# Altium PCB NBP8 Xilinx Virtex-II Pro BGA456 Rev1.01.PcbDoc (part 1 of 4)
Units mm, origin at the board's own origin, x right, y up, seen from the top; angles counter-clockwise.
Board outline 69 x 99.5 mm, 8 copper layers (Top Layer, InternalPlane1, InternalPlane2, MidLayer1, MidLayer2, MidLayer3, MidLayer4, Bottom Layer), stack 1.545 mm thick; 164 components, 314 nets, 1132 pads, 807 vias.
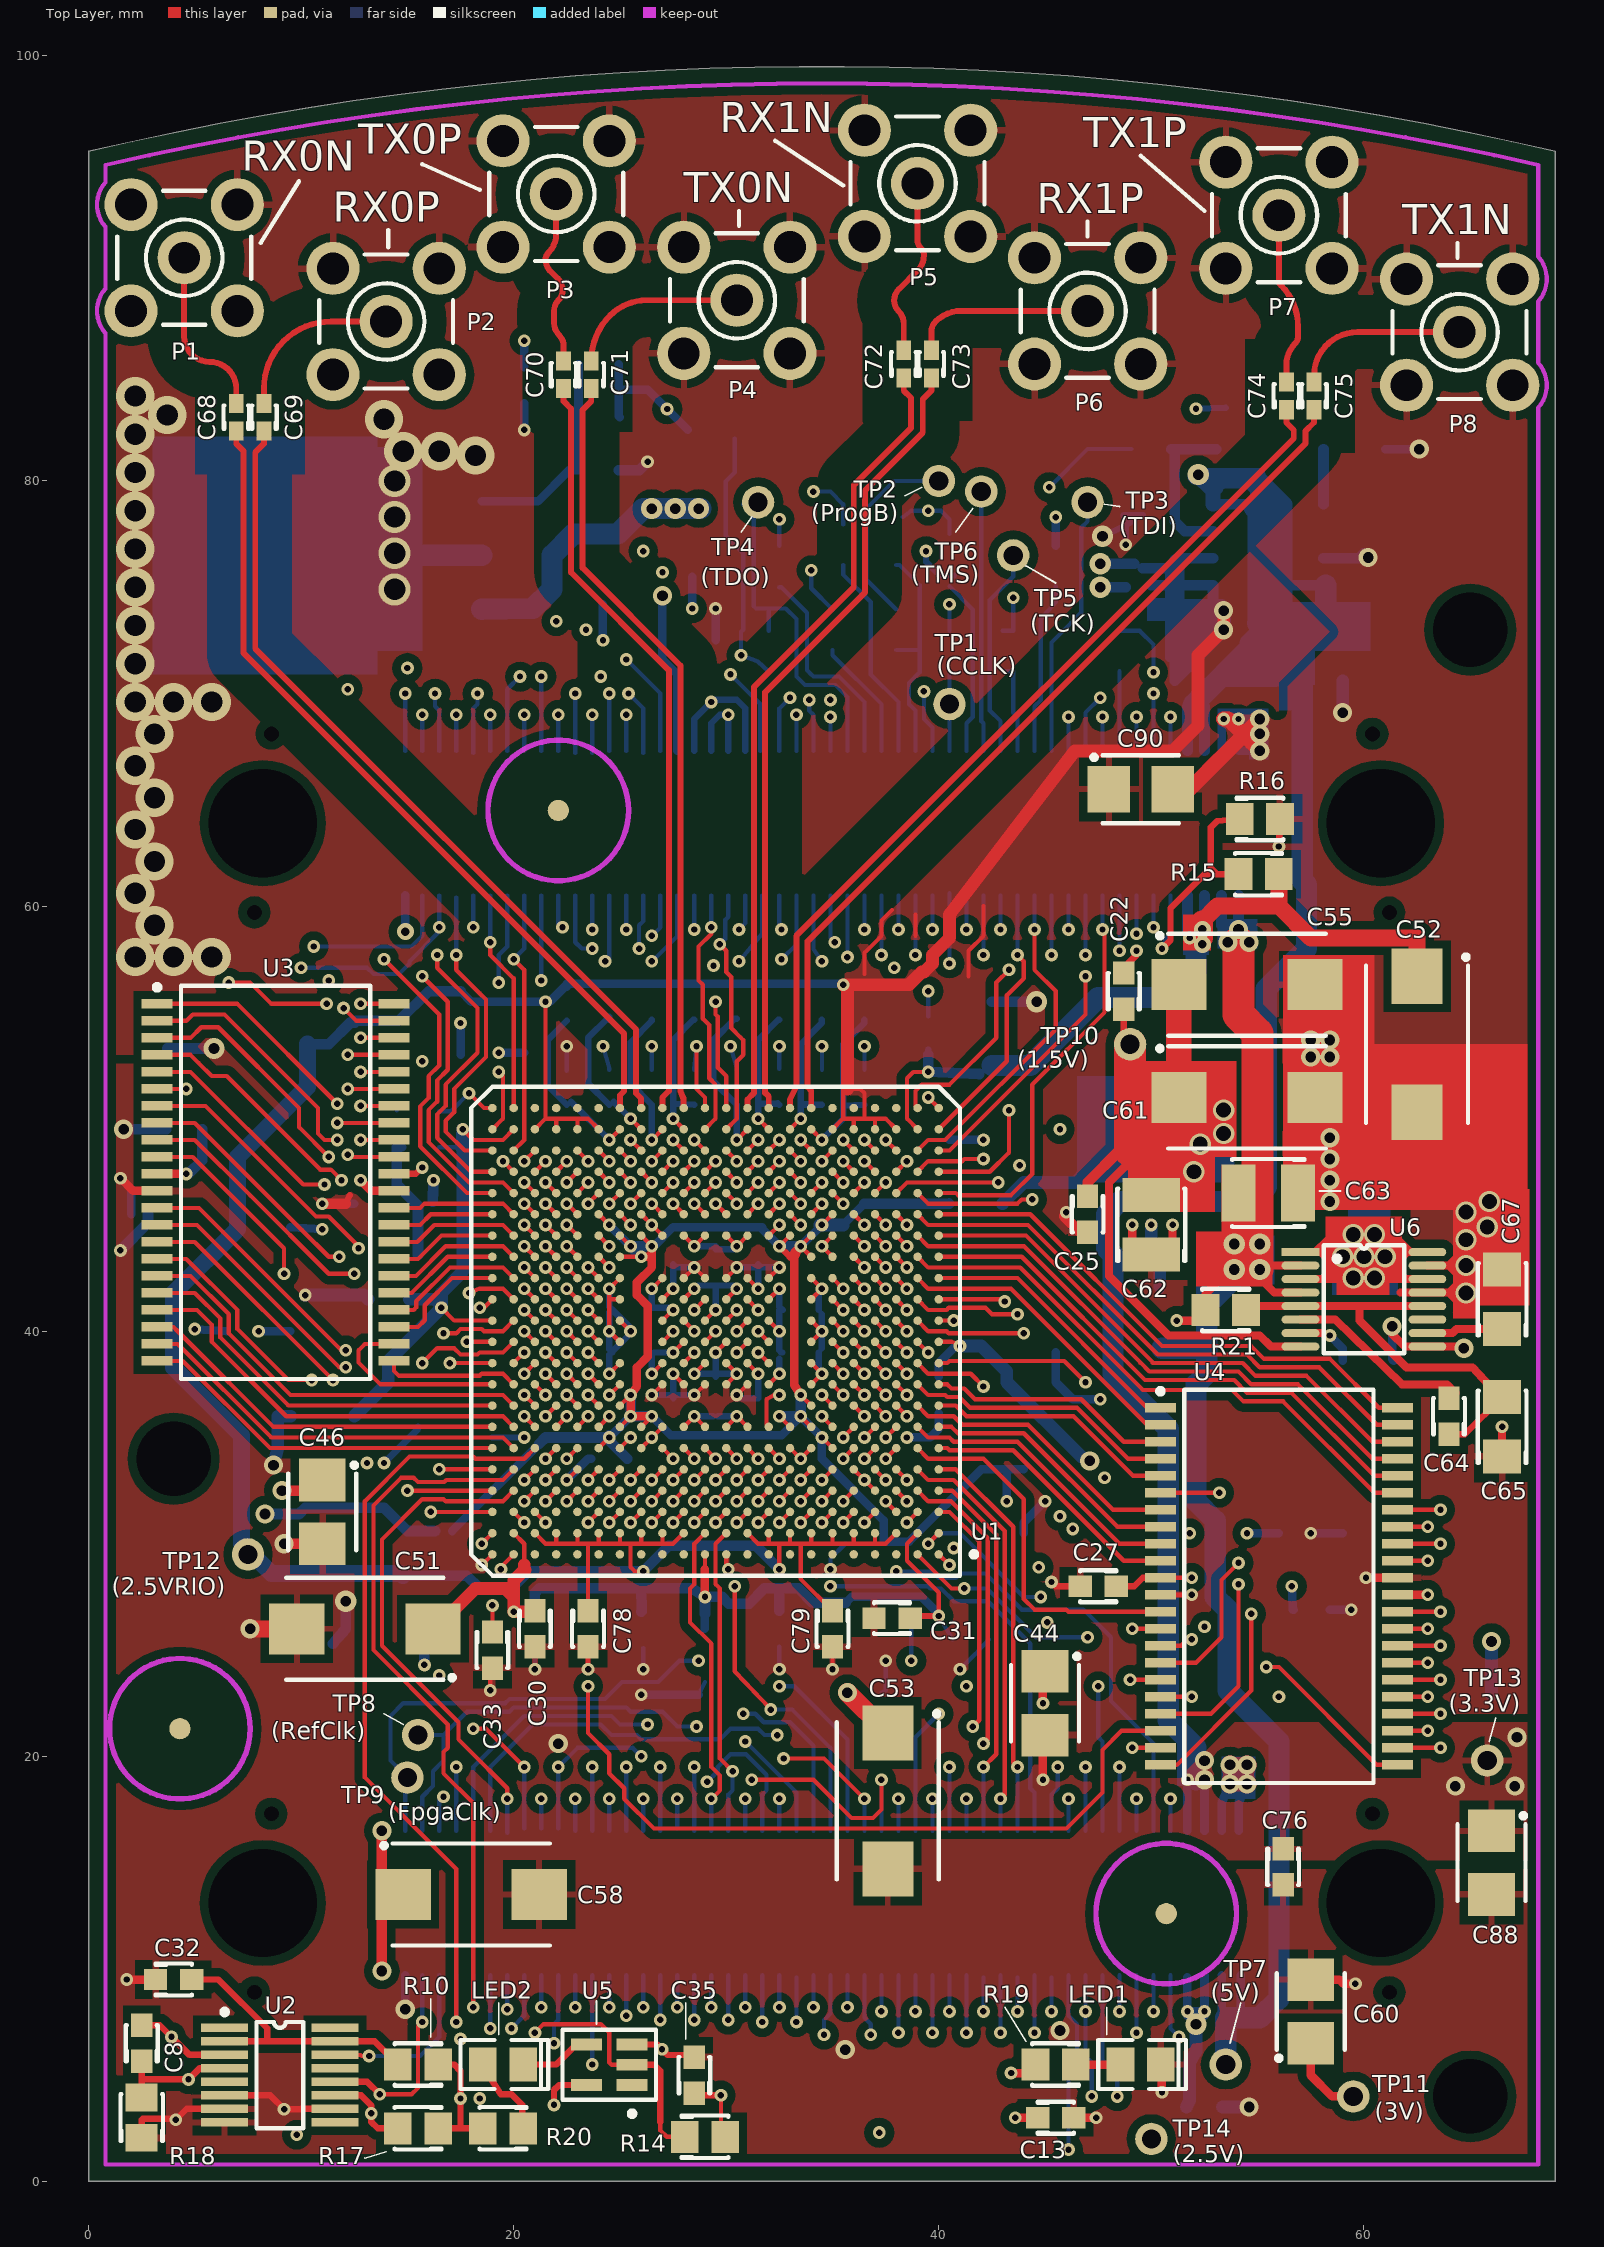
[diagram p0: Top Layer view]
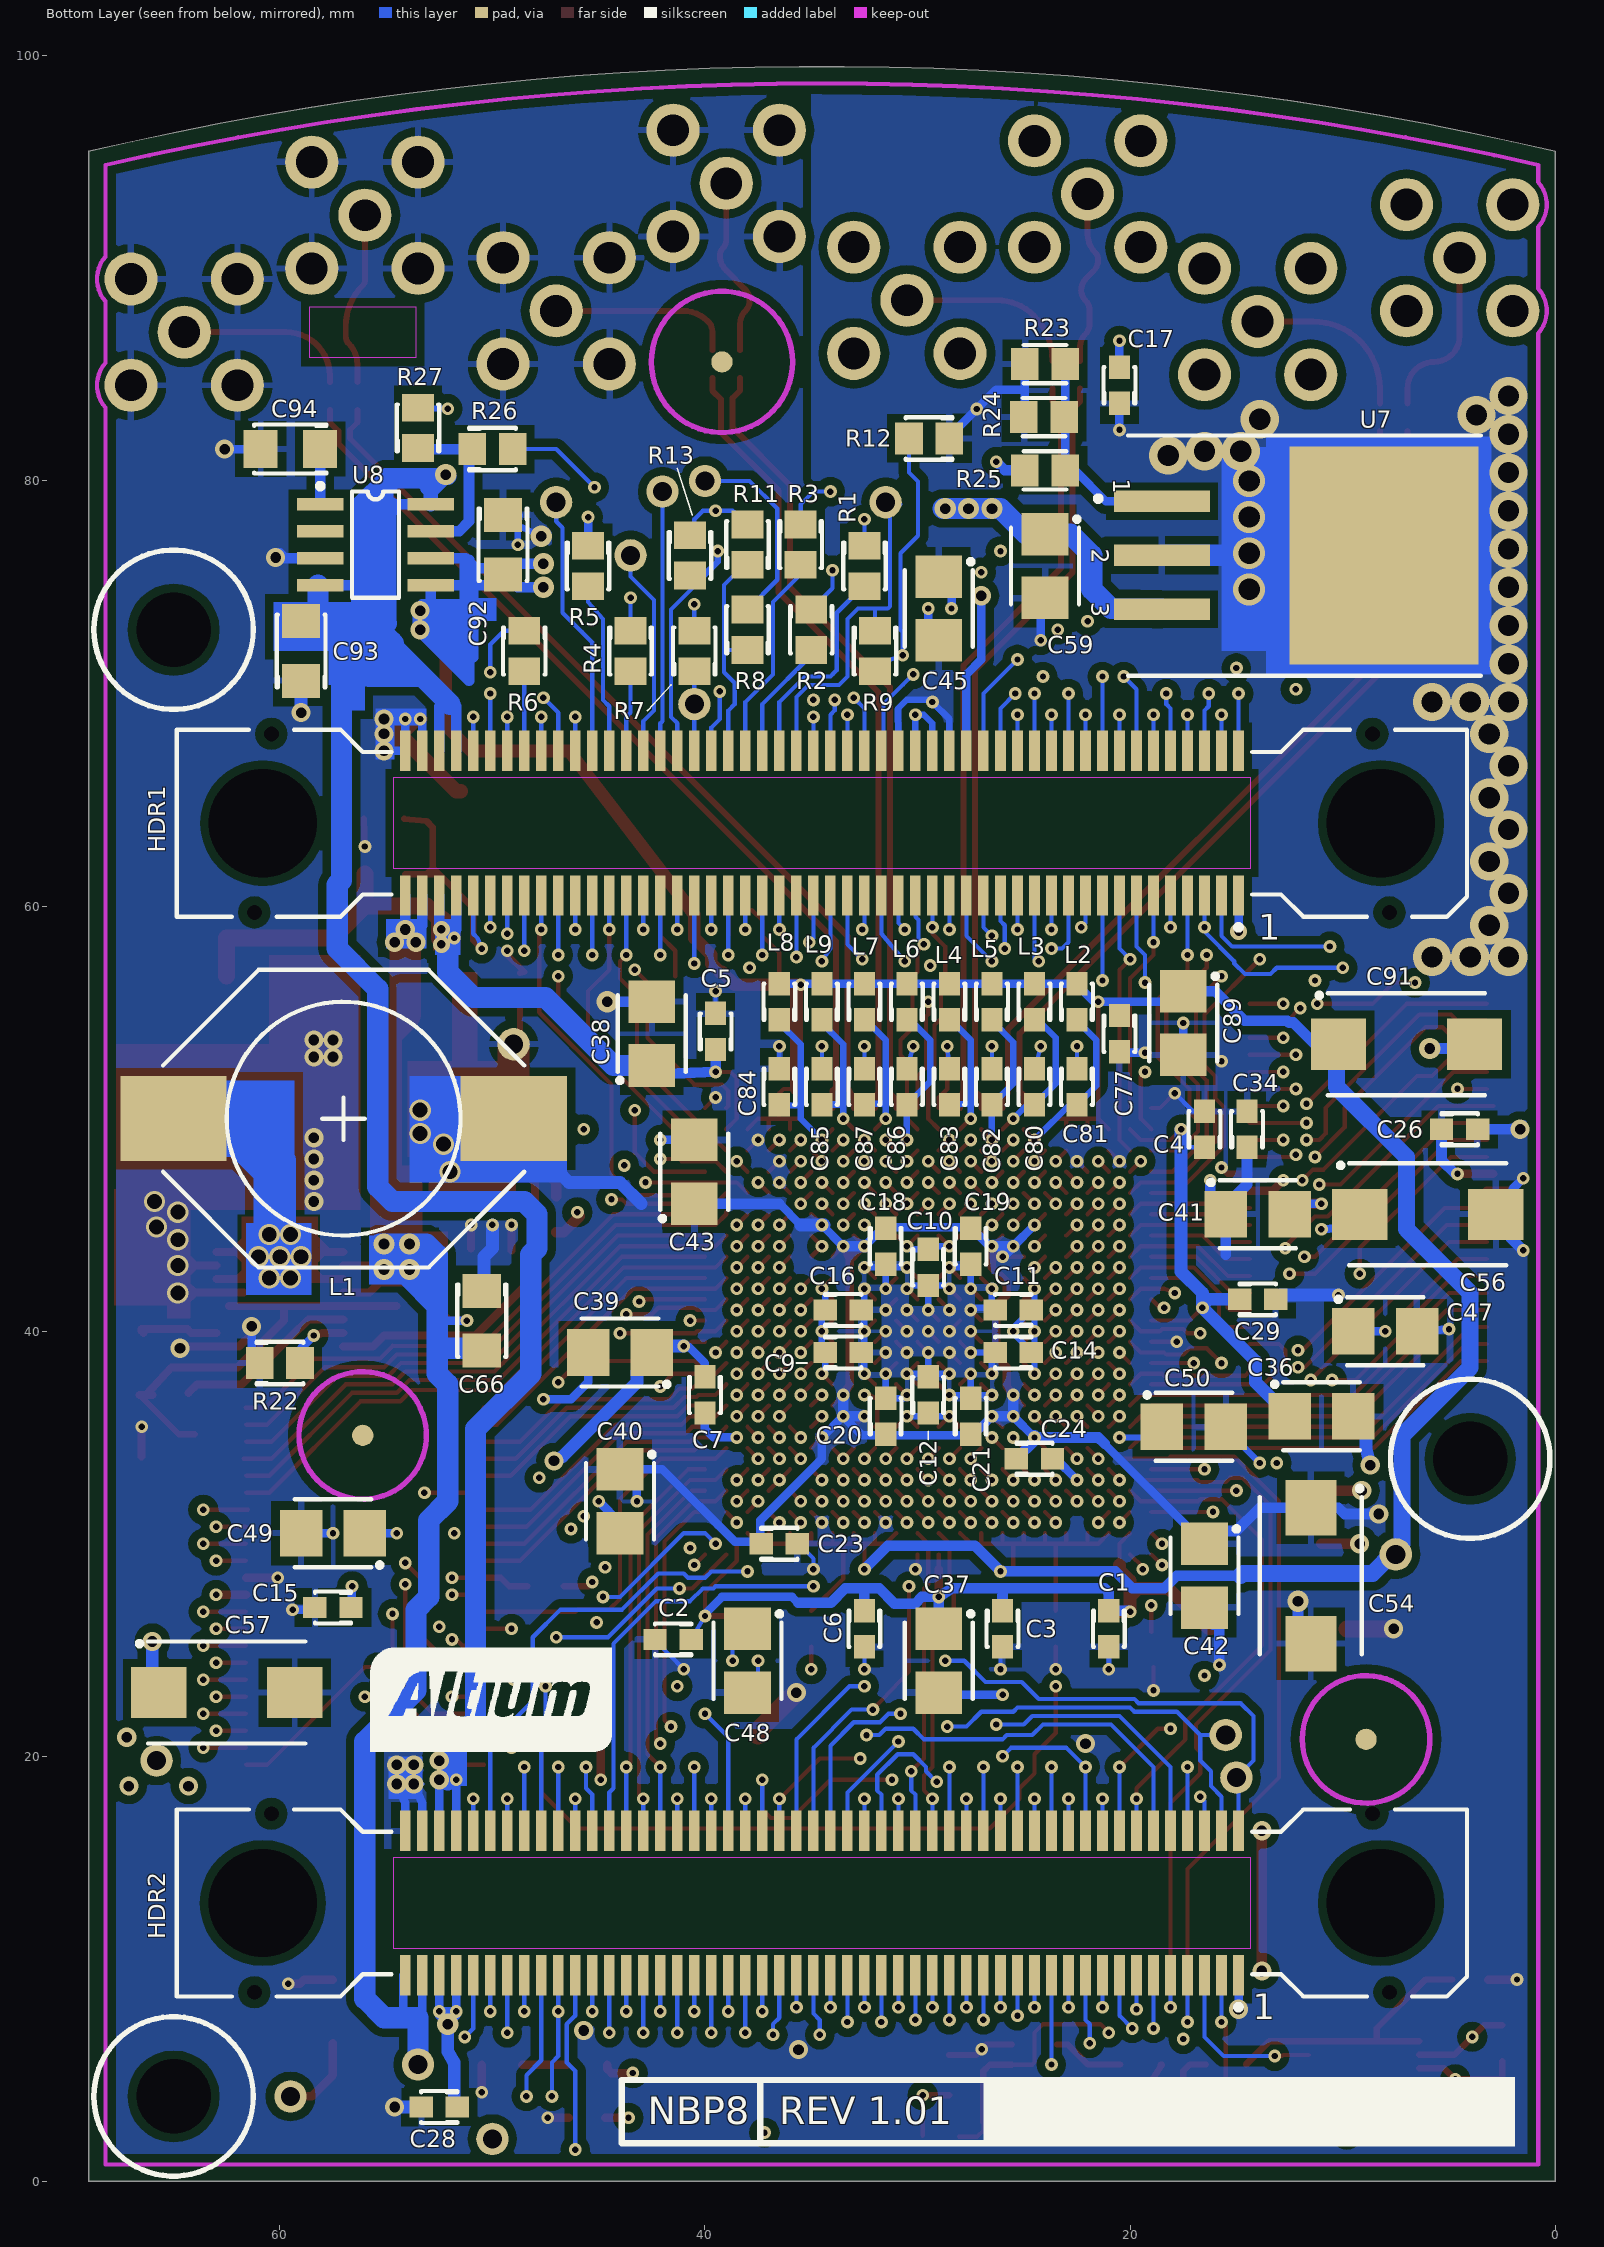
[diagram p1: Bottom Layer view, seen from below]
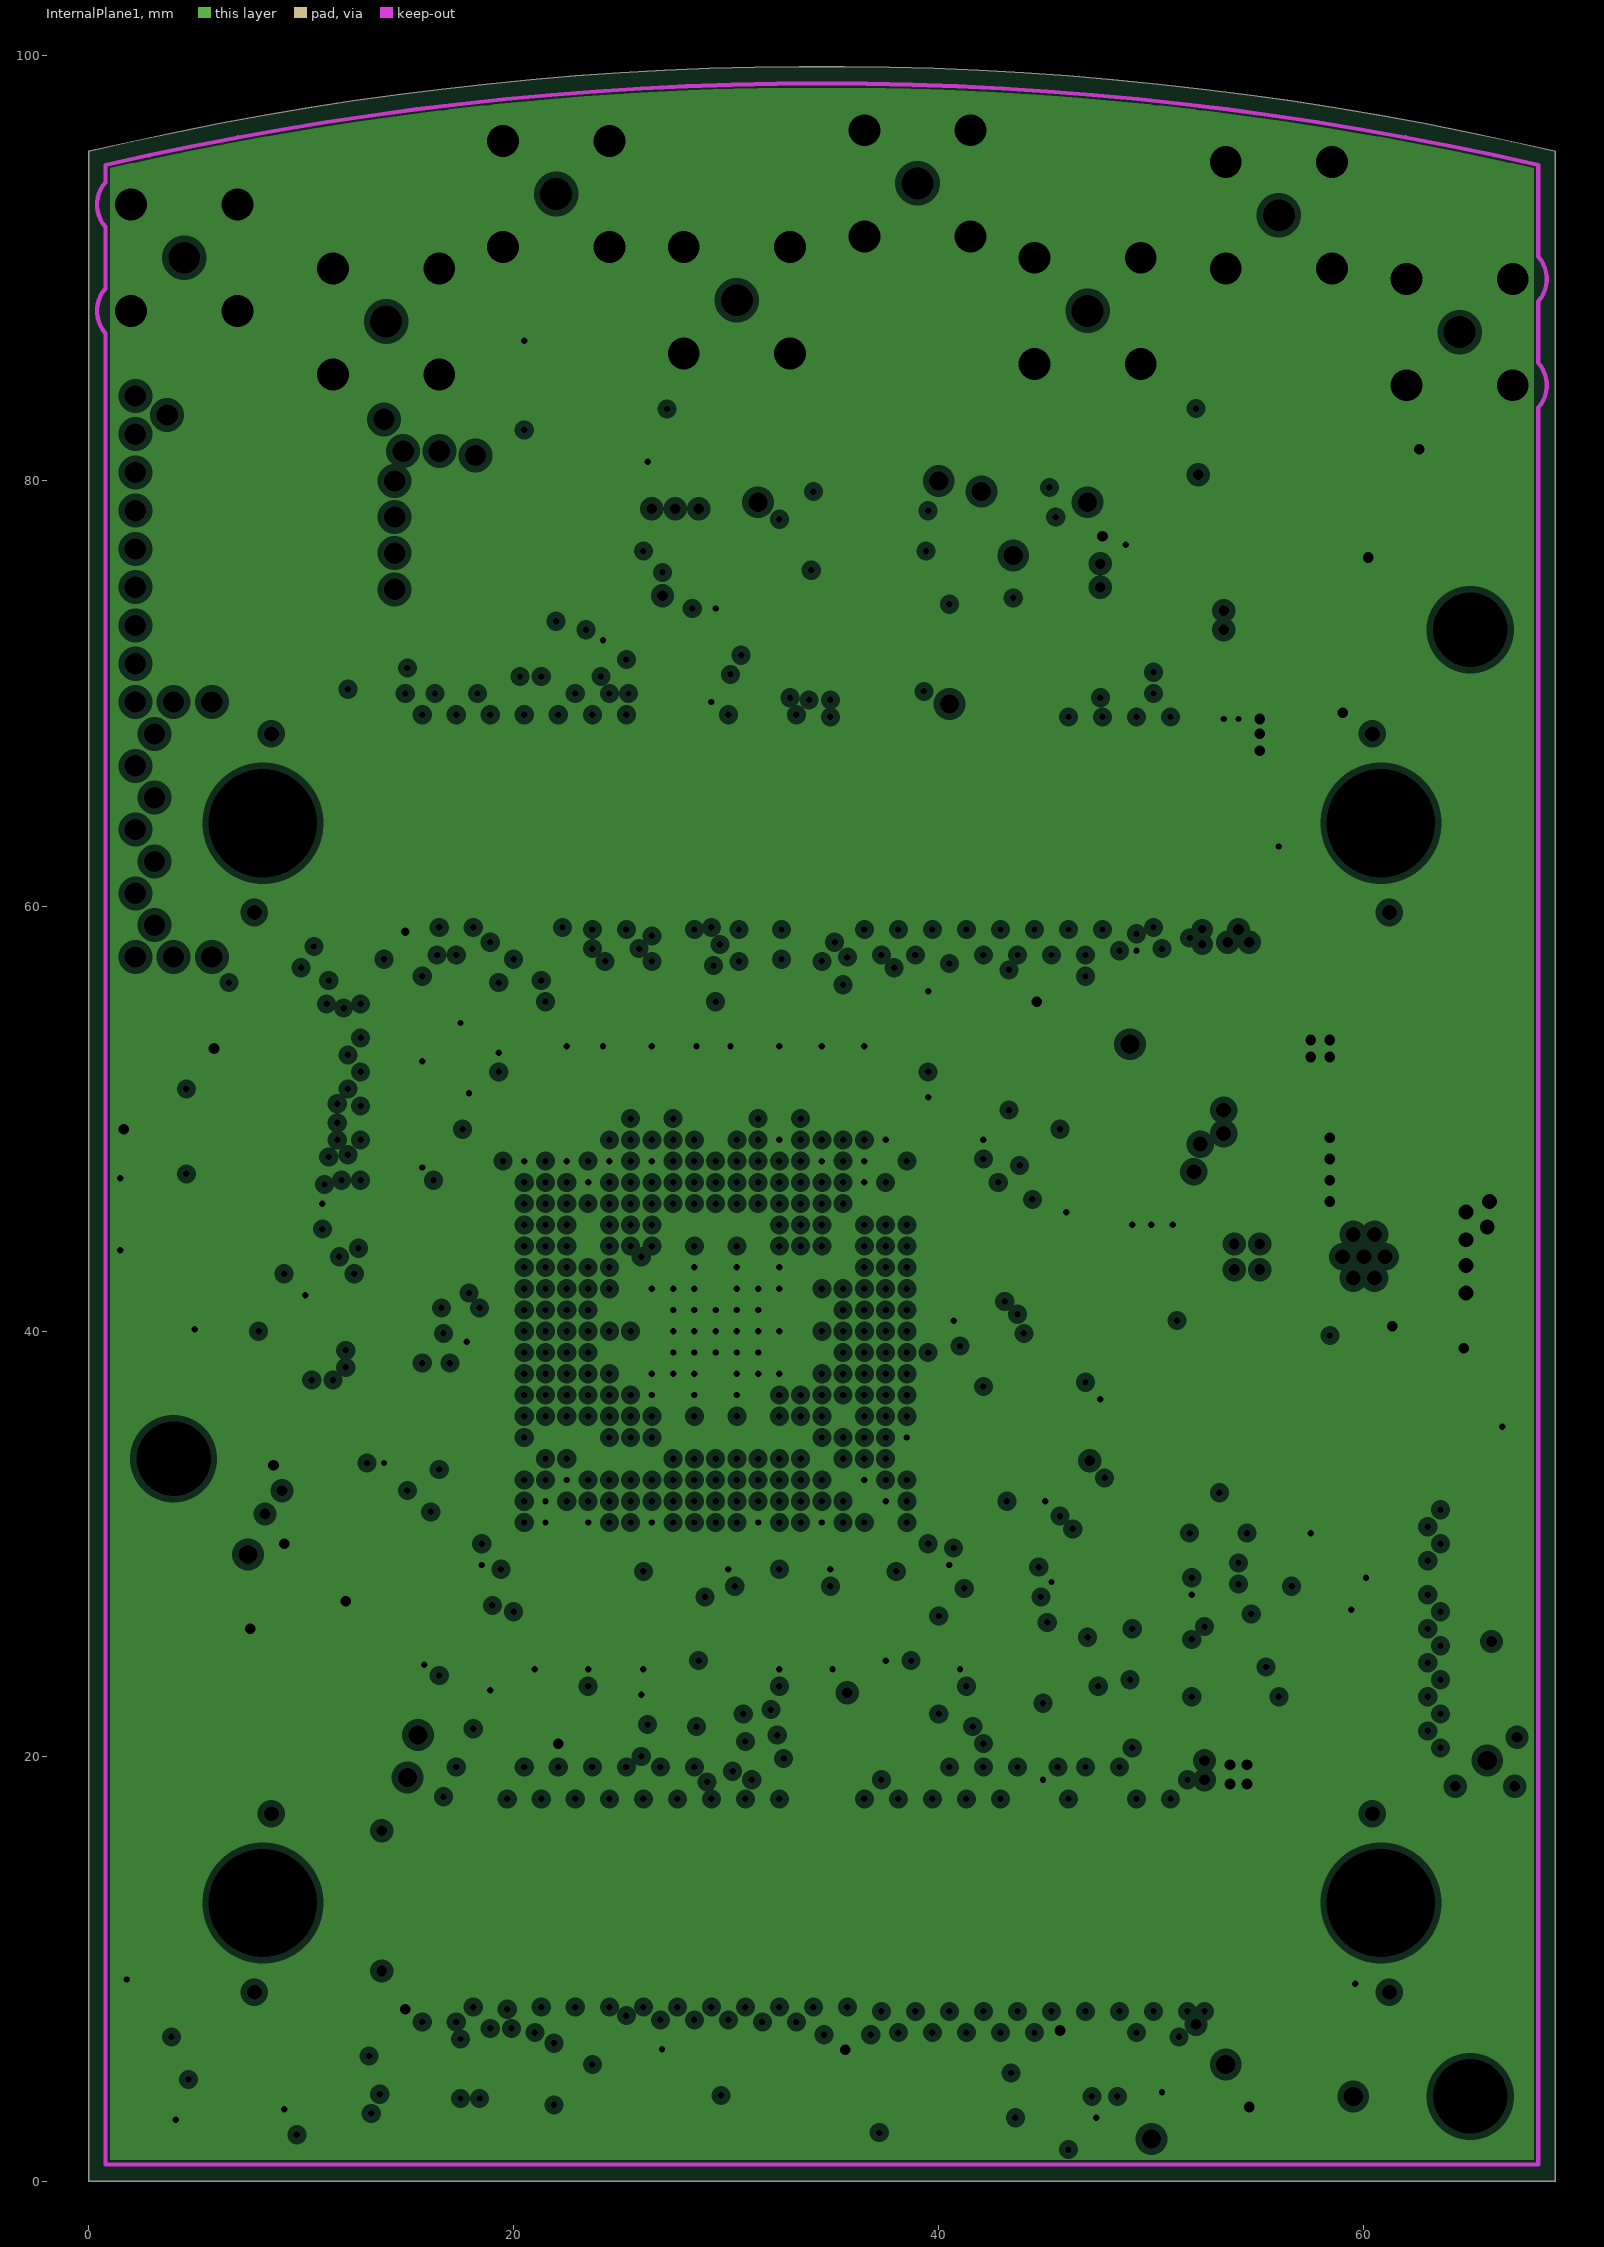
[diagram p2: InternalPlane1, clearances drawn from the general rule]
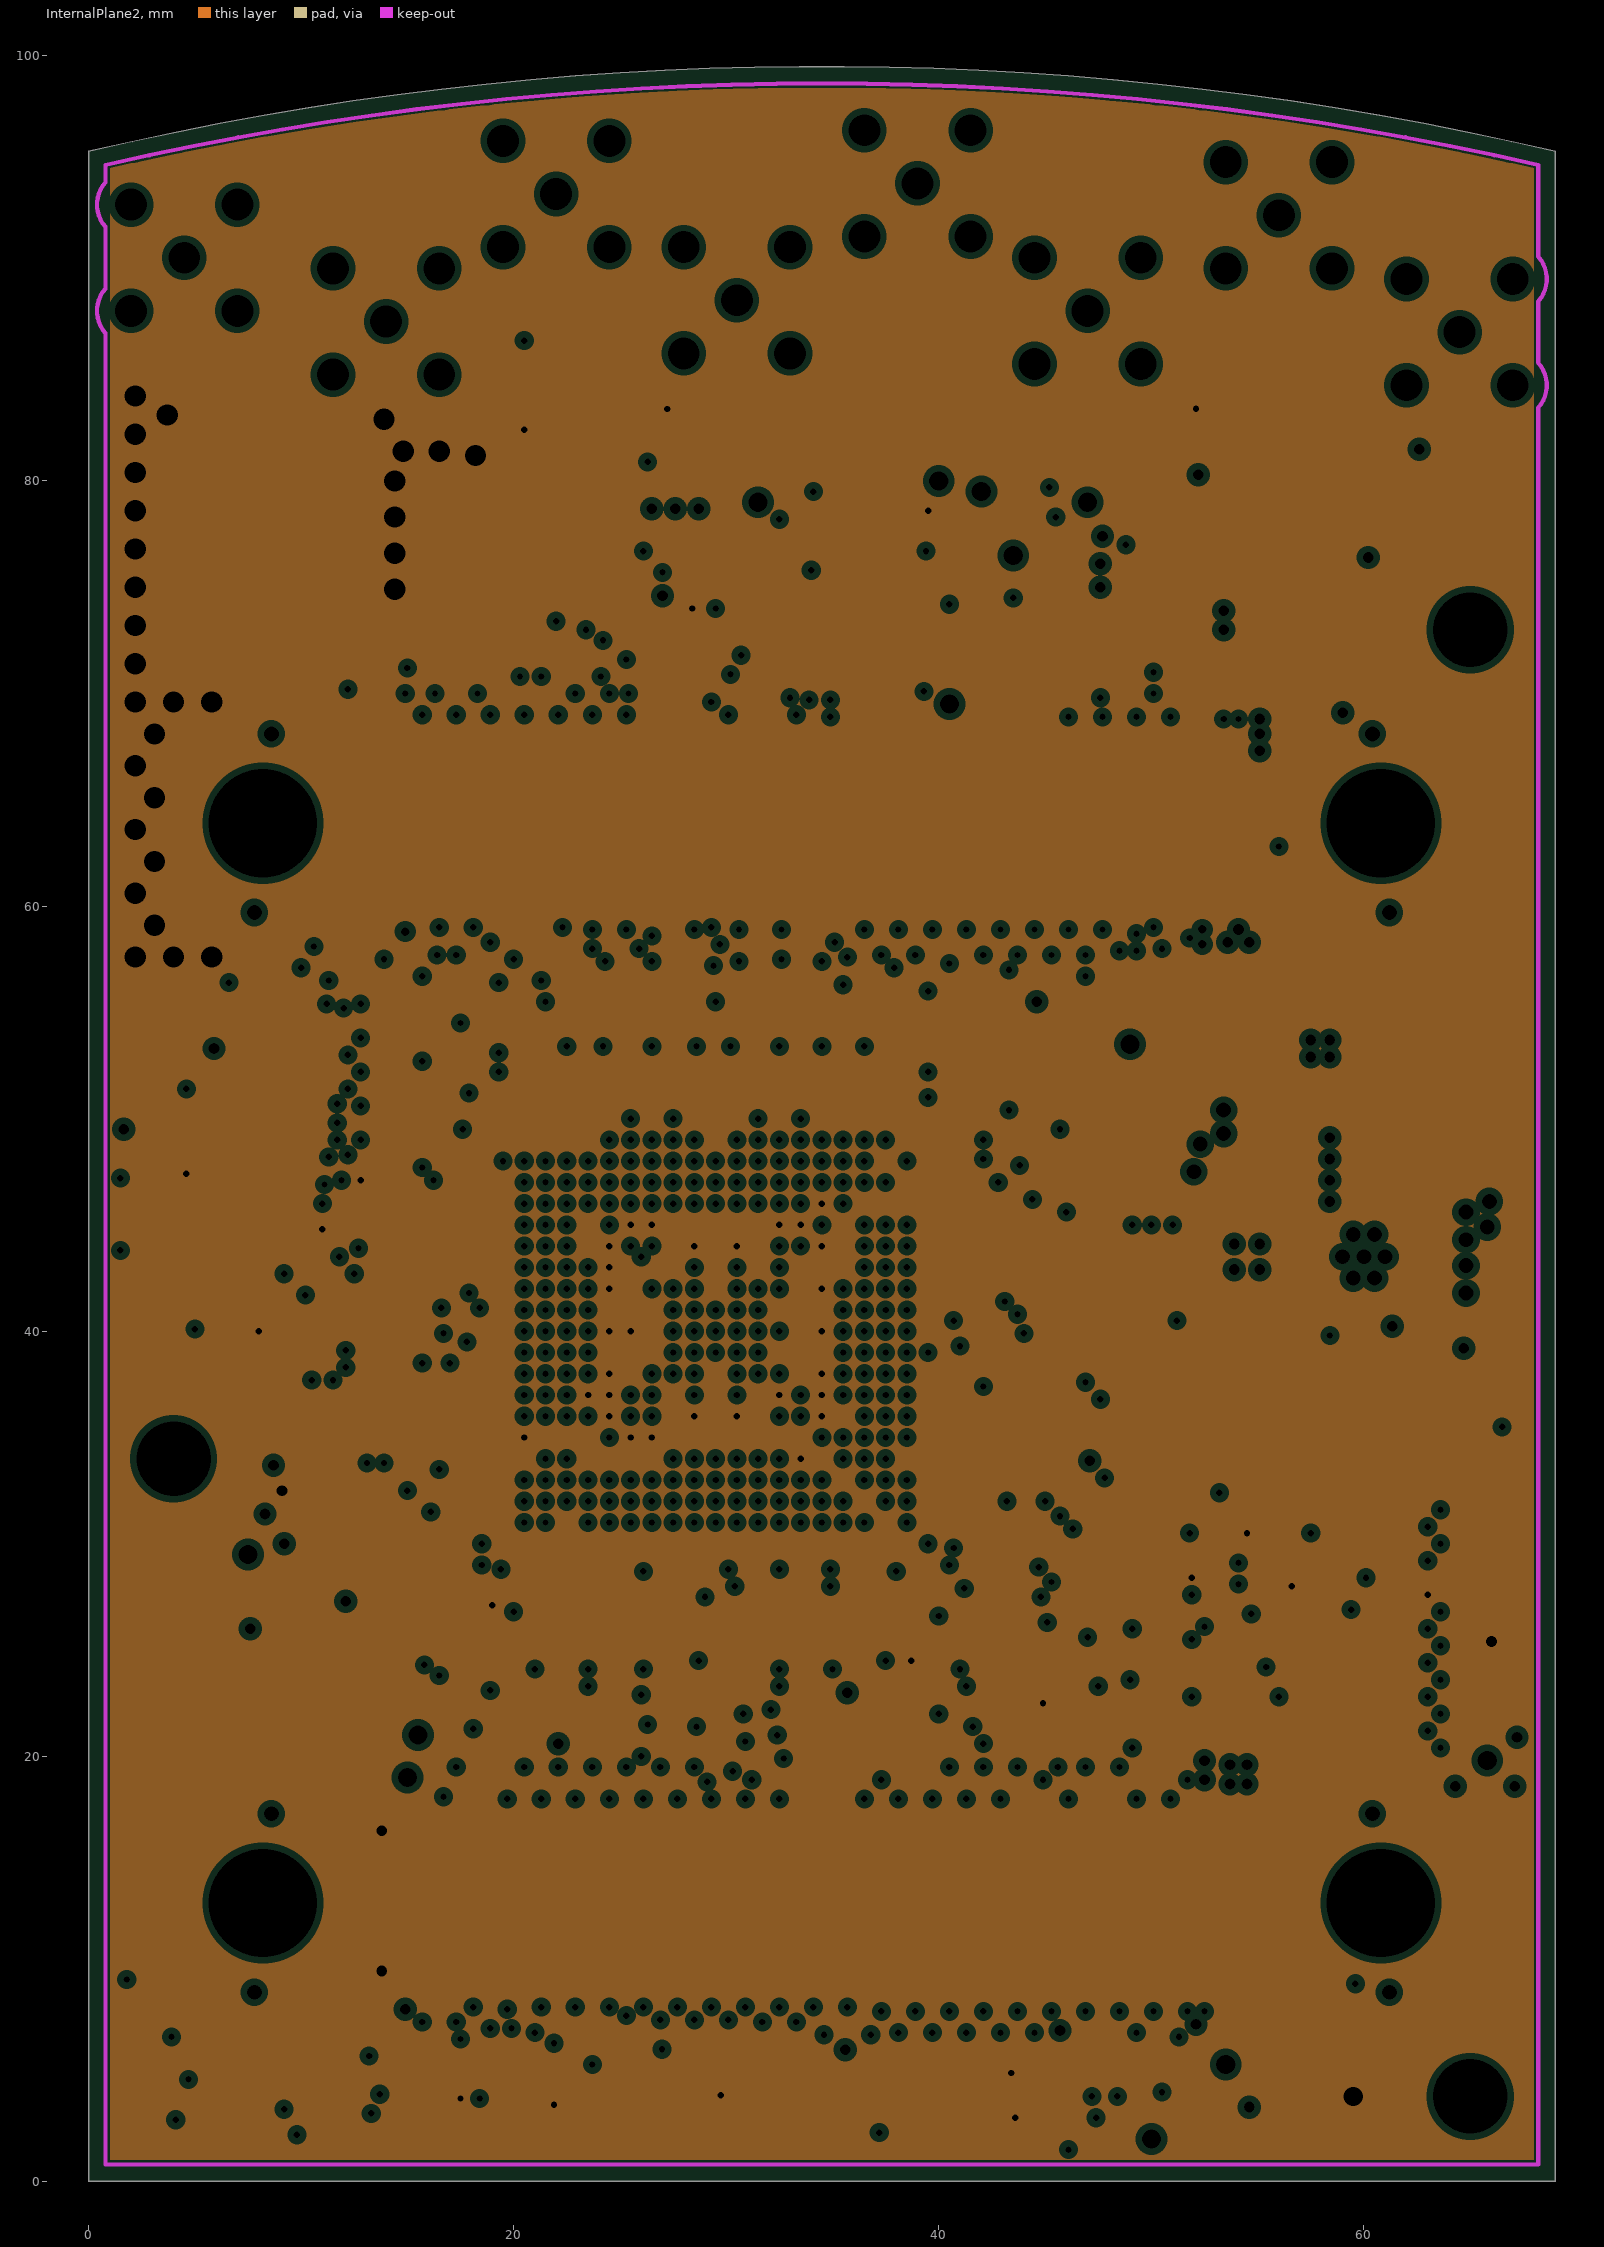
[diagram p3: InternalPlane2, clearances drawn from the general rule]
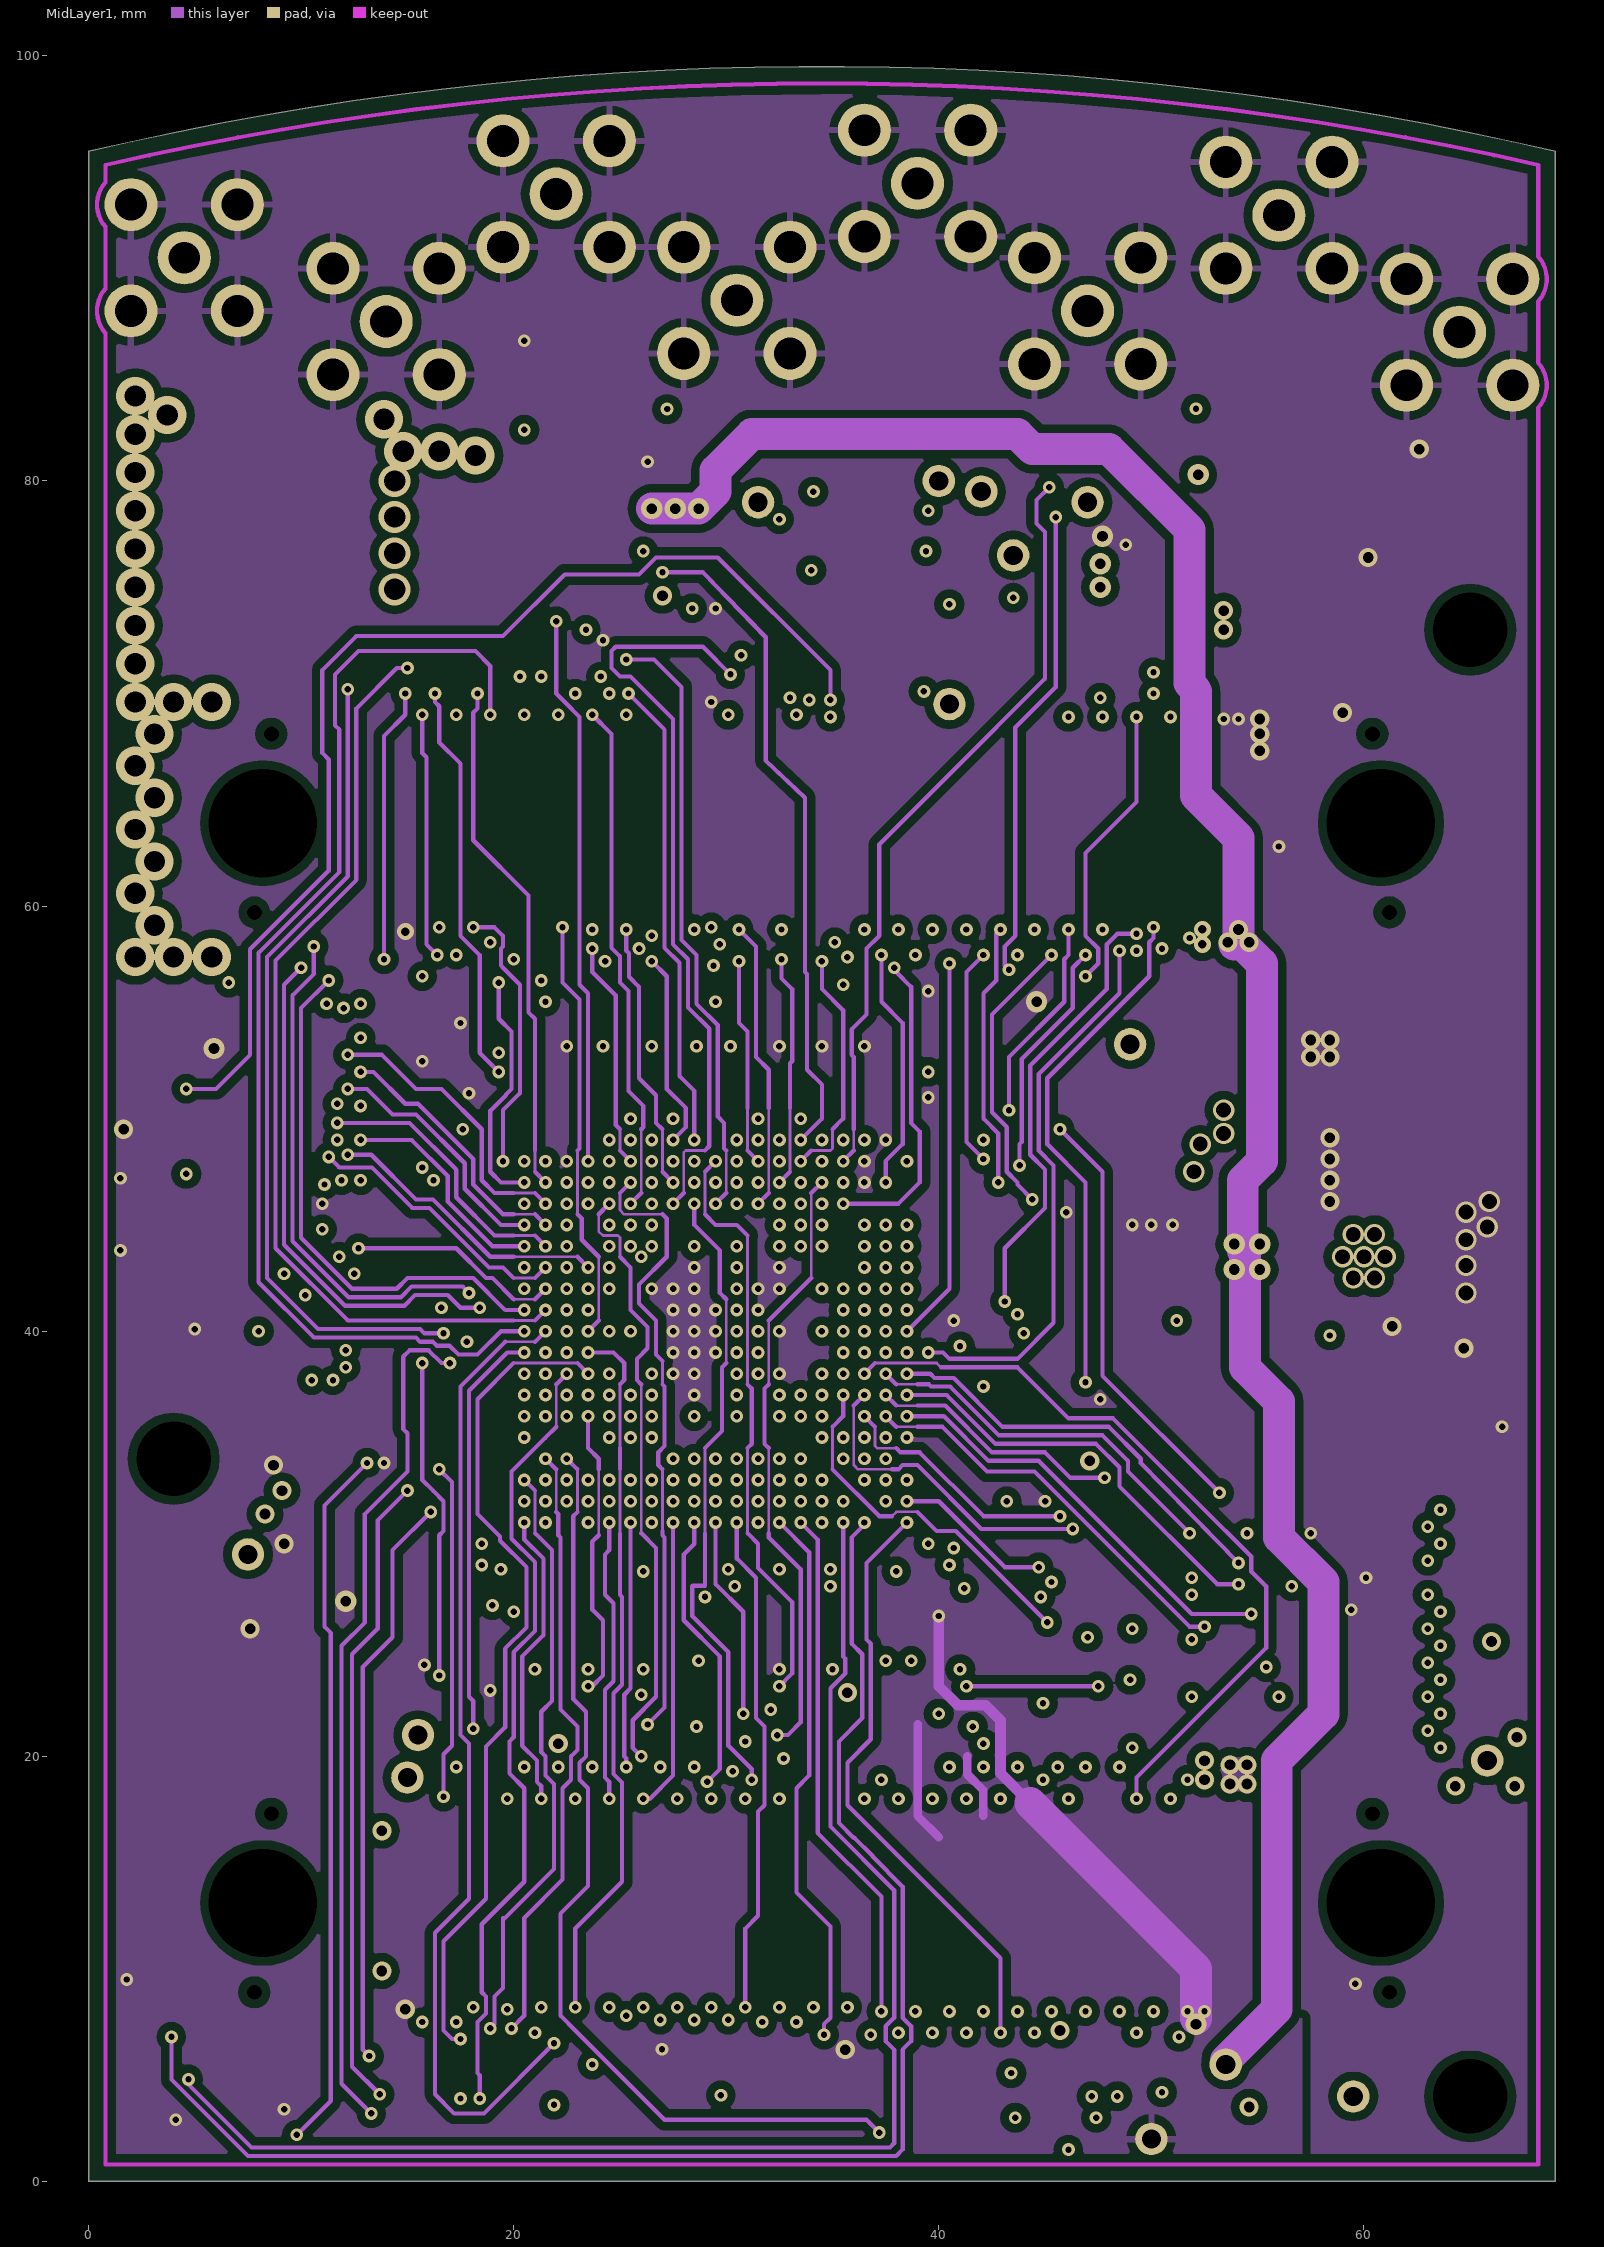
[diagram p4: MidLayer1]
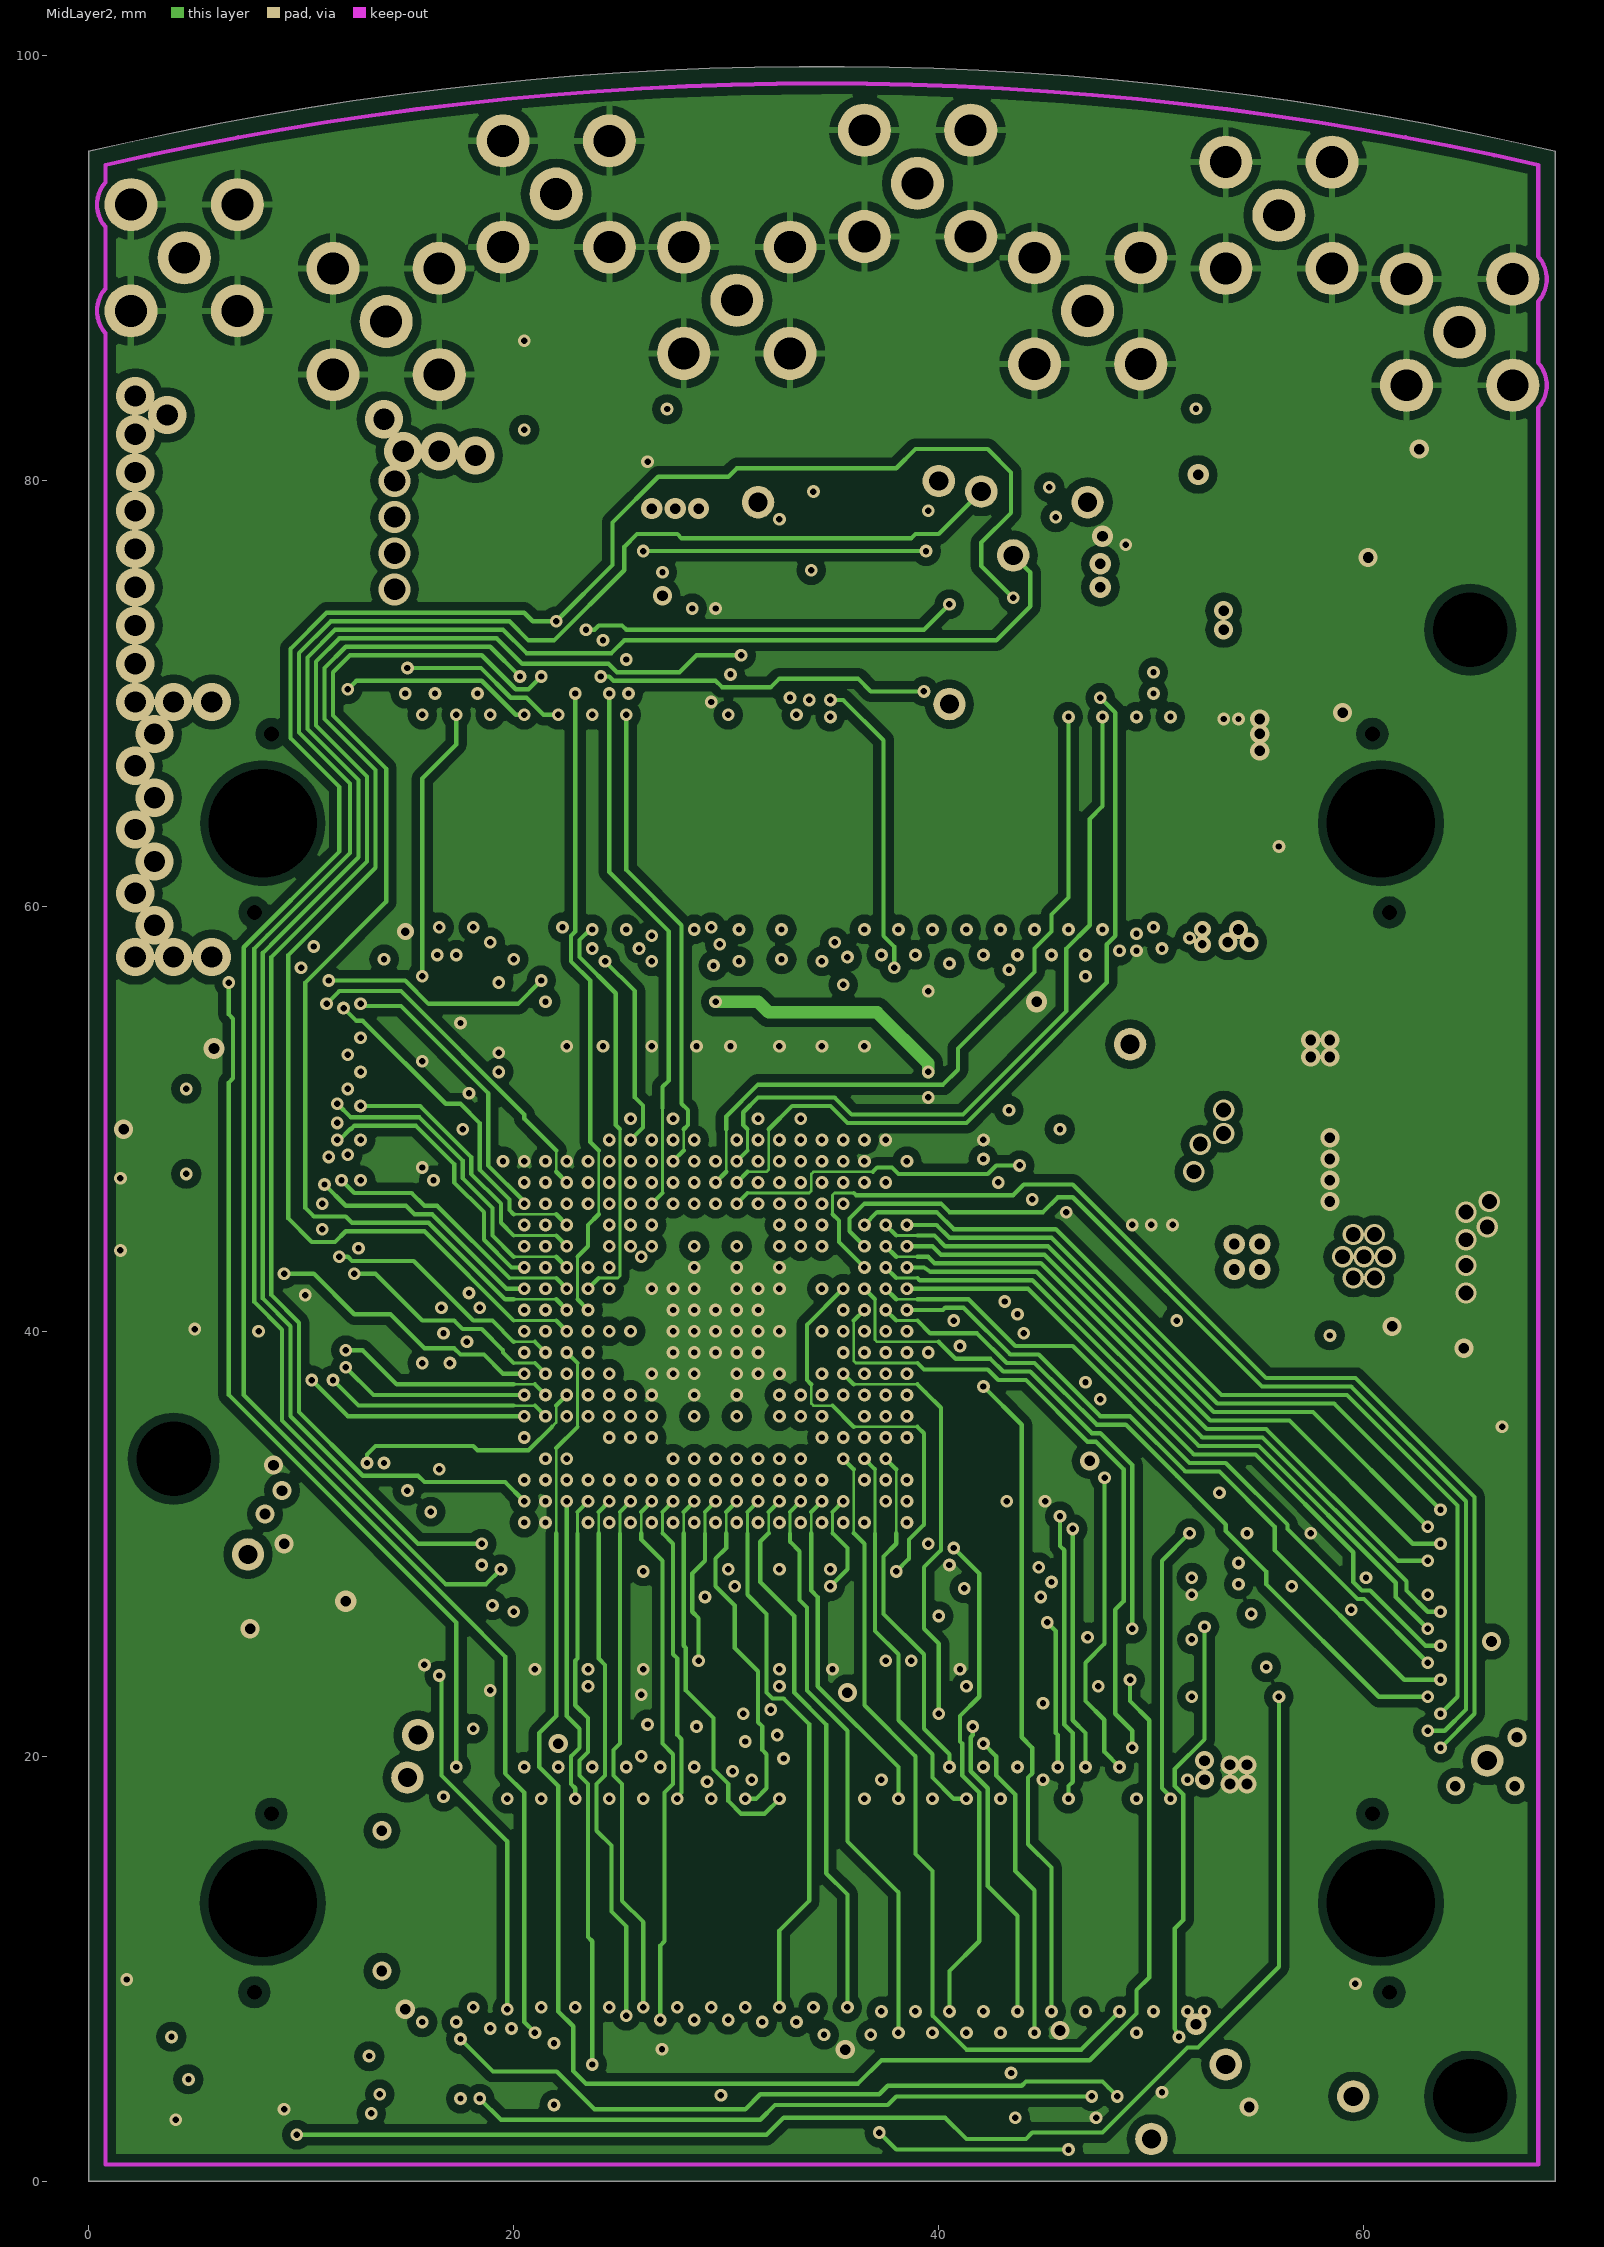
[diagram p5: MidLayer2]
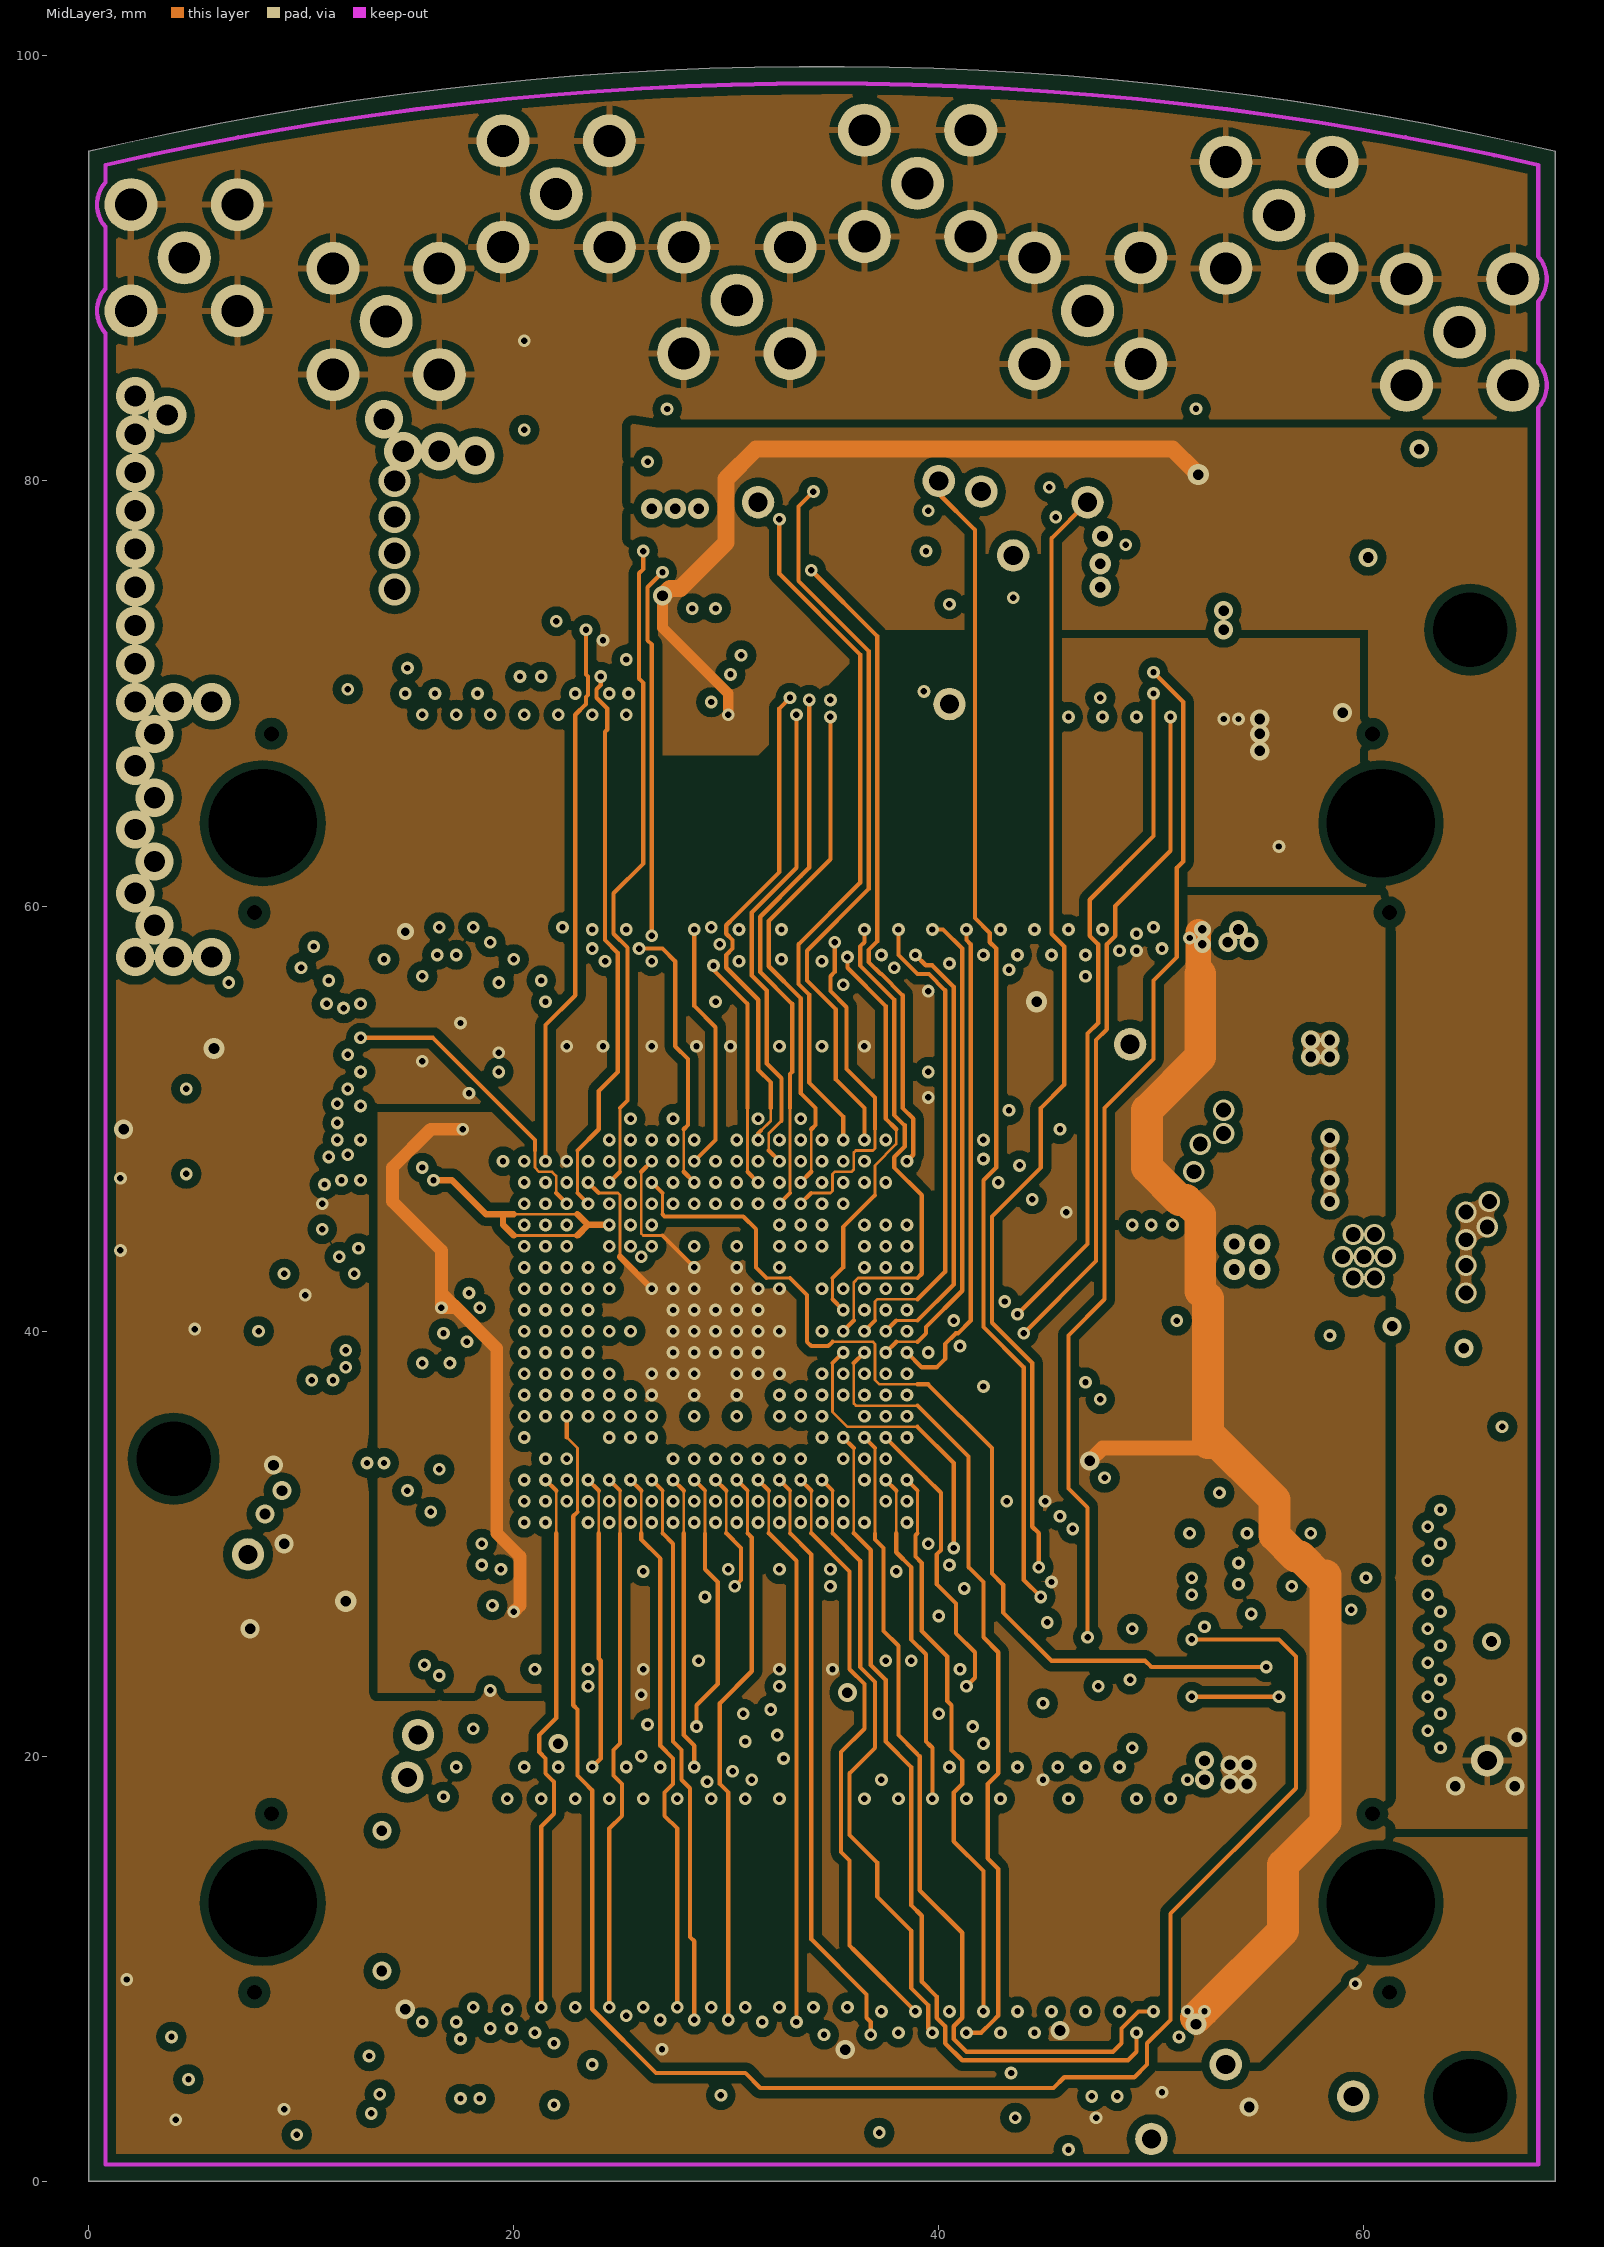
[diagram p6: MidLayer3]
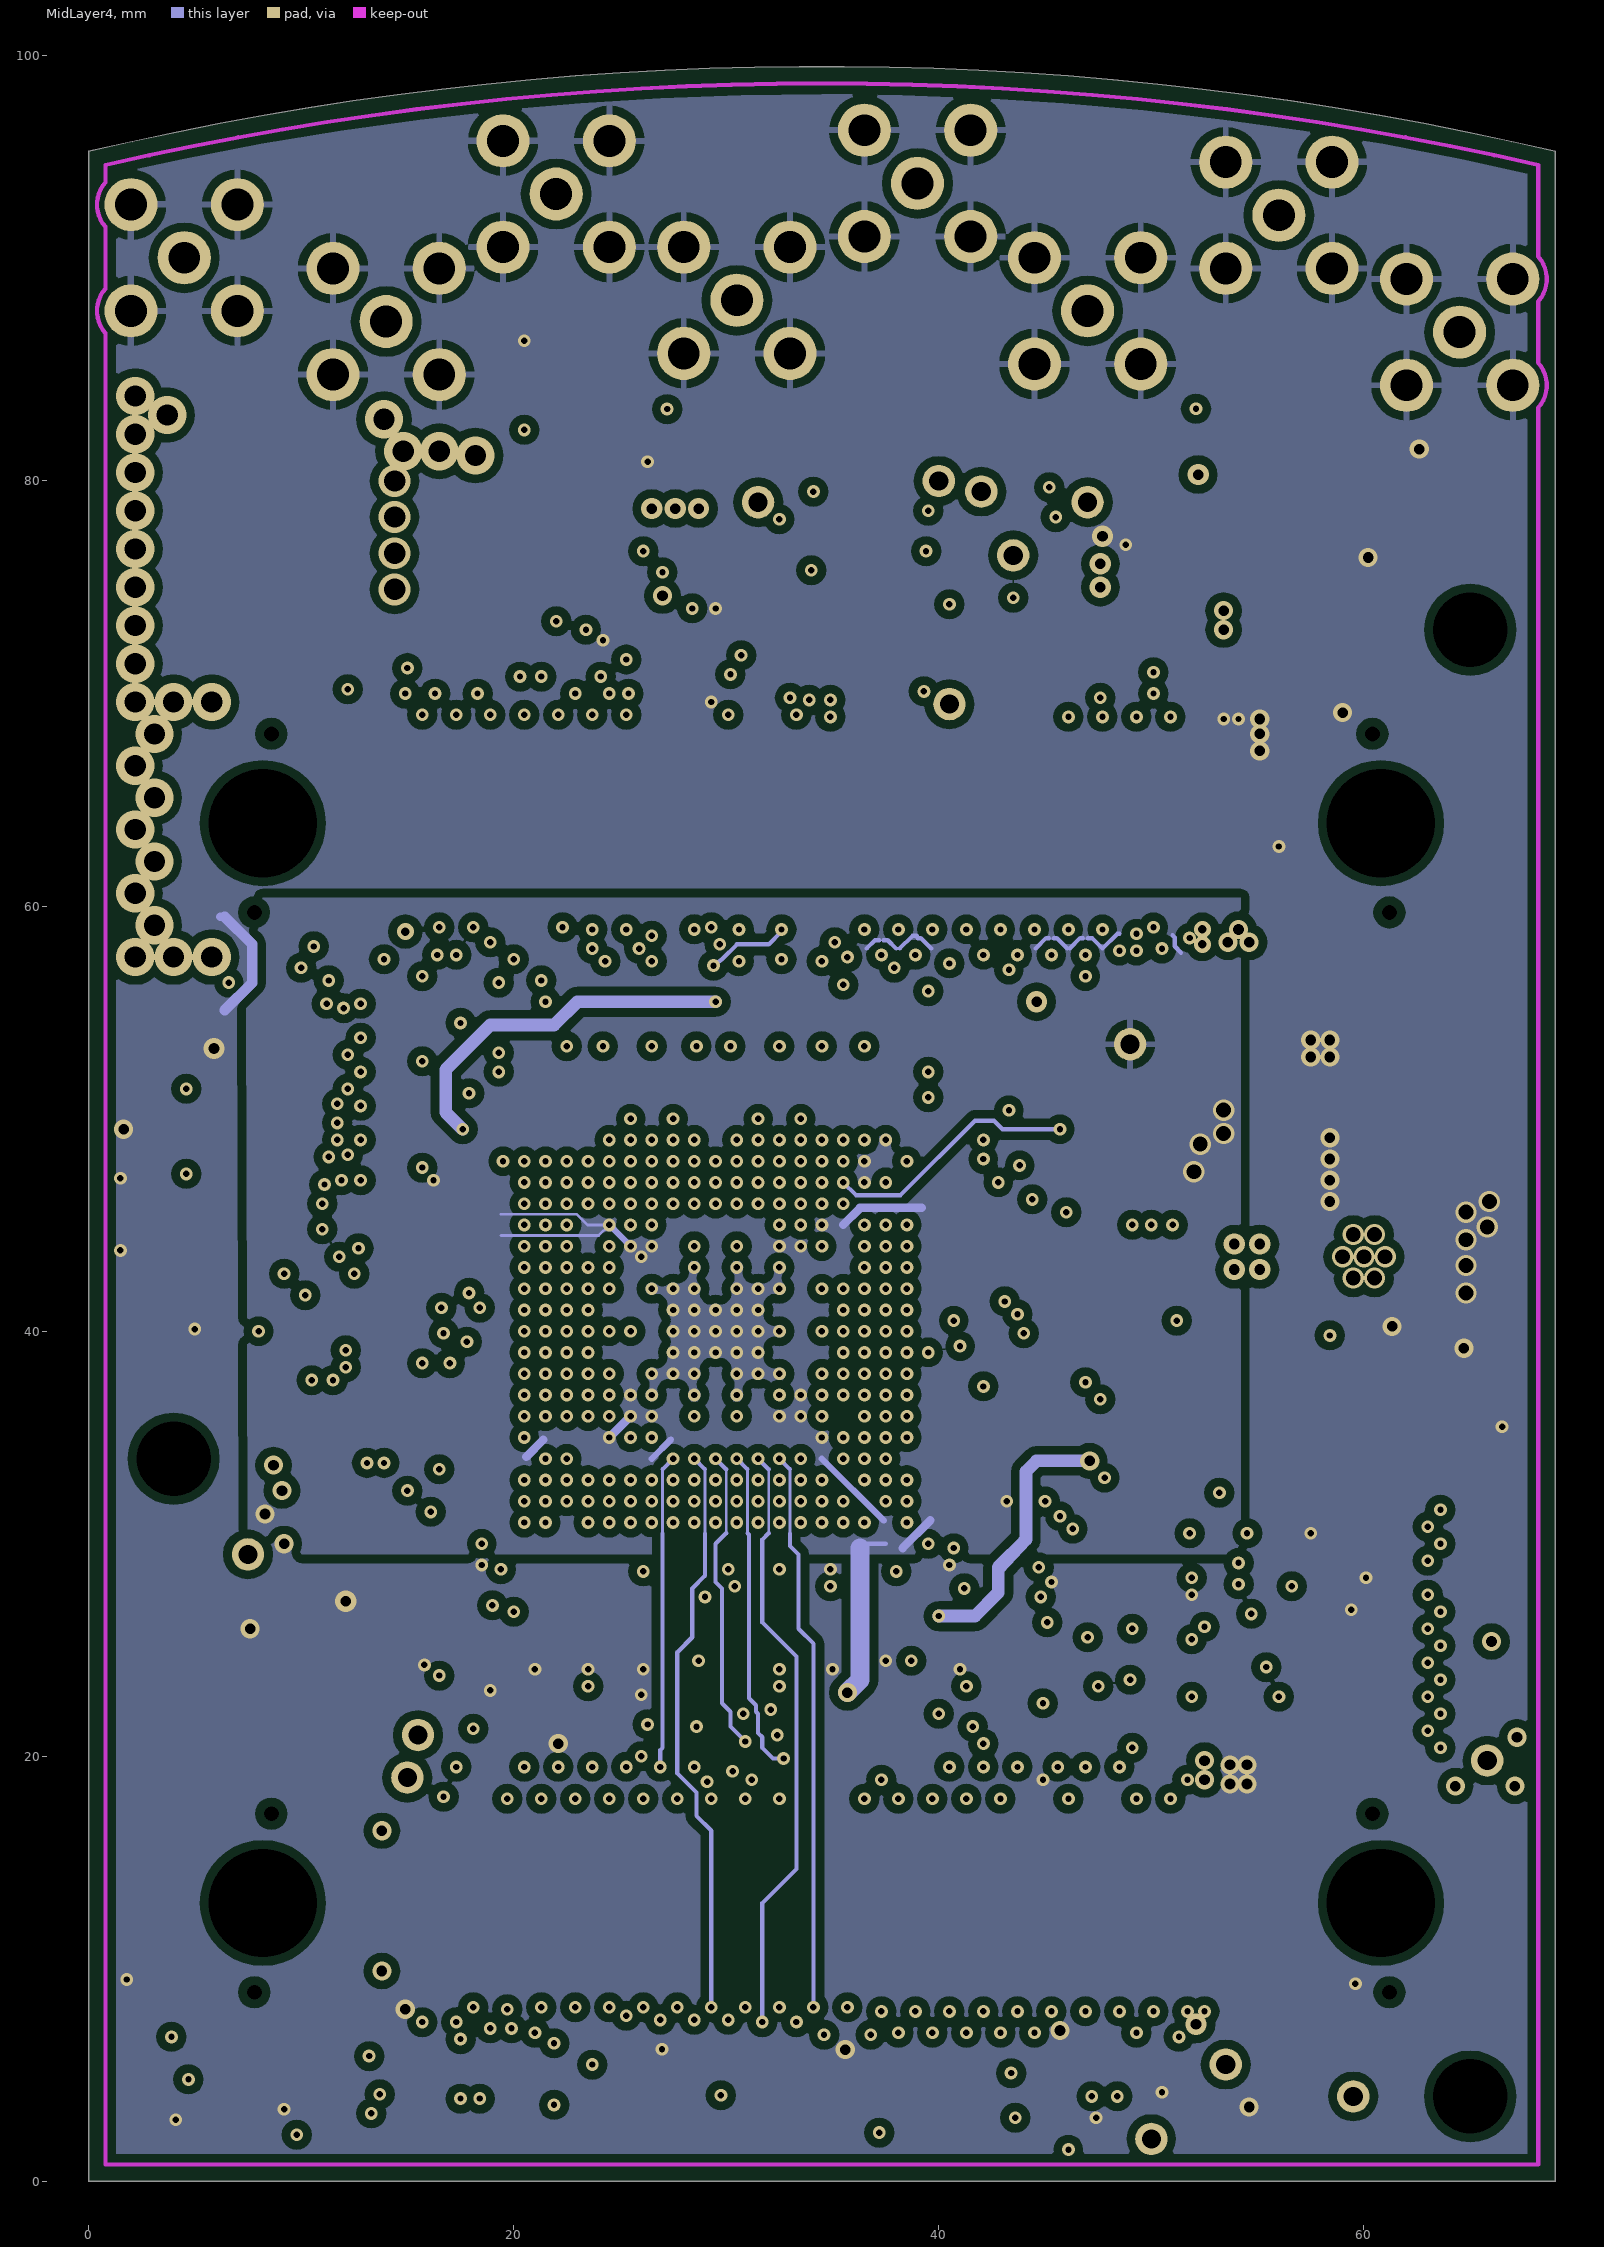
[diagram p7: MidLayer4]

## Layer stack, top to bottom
Top Layer: signal copper 0.018
Dielectric: core 0.2159, FR-4, Dk 4.5
InternalPlane1: plane copper 0.0356, net GND
Dielectric: prepreg 0.1524, FR-4, Dk 4.5
InternalPlane2: plane copper 0.0356, net VCC
Dielectric: core 0.2032, FR-4, Dk 4.5
MidLayer1: signal copper 0.0356
Dielectric: prepreg 0.1524, FR-4, Dk 4.5
MidLayer2: signal copper 0.0356
Dielectric: core 0.2032, FR-4, Dk 4.5
MidLayer3: signal copper 0.0356
Dielectric: prepreg 0.1524, FR-4, Dk 4.5
MidLayer4: signal copper 0.0356
Dielectric: core 0.2159, FR-4, Dk 4.5
Bottom Layer: signal copper 0.018

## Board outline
0,-0.001 cw(c0,0) -0.001,0 0,95.499 0,95.5 cw(c0.001,95.5) 0,95.501 cw(c34.5,-51.301) 69,95.501 cw(c68.999,95.5) 69,95.5 69,95.499 69.001,0 cw(c69,0) 69,-0.001

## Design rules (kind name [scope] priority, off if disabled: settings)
Clearance "Rocket I/O -> Top Layer Plane Clearance" [InNetClass('ROCKET_IO_LINES') vs OnLayer('Top Layer') And InPolygon] p1: gap=1.6
Clearance "Polygon Clearance" [InPoly] p2: gap=0.4
Clearance "TX1 Clearance" [InNetClass('TX1') vs InNetClass('TX1')] p3: gap=0.254
Clearance "RX1 Clearance" [InNetClass('RX1') vs InNetClass('RX1')] p4: gap=0.254
Clearance "RX0 Clearance" [InNetClass('RX0') vs InNetClass('RX0')] p5: gap=0.254
Clearance "TX0 Clearance" [InNetClass('TX0') vs InNetClass('TX0')] p6: gap=0.254
Clearance "Via --> Mid Layer Clearance" [IsVia vs OnMid] p7: gap=0.127
Clearance "Pad to Via Clearance" [IsPad vs IsVia] p8: gap=0.2
Clearance "General Clearance" [All] p9: gap=0.2
ComponentClearance ComponentClearance_General [Not InComponentClass('Rocket Decoupling Caps') vs Not InComponentClass('Rocket Decoupling Caps')] p1: gap=0.2 collisioncheckmode=3 verticalgap=0.254 showdistances=FALSE
ComponentClearance ComponentClearance_Default [All] p2 off: gap=0.2 collisioncheckmode=3 verticalgap=0.254 showdistances=FALSE
DiffPairsRouting [All] p1: maxlimit=0.254 minlimit=0.254 mostfreqgap=0.254 maxuncoupledlength=12.7
FabricationTestPointUsage TestPointUsage [All] p1 off: valid=0 allowmultiple=FALSE
FabricationTestpoint Testpoint [All] p1 off: side=3 testpointundercomponent=TRUE minsize=1.016 maxsize=2.54 preferedsize=1.524 minholesize=0 maxholesize=1.016 preferedholesize=0.813 testpointgrid=0.025 allowsidetop=TRUE allowsidebottom=TRUE usegrid=TRUE gridtolerance=0
FanoutControl Fanout_Small [CompPinCount < 5] p4: bgadir=Out bgaviamode=Centered fanoutstyle=Auto fanoutdirection=OutThenIn viagrid=0.025 // Fanout_Small (Default Rule)
HoleSize [All] p1: absolutevalues=TRUE maxlimit=10 minlimit=0.3 maxpercent=80.000 minpercent=20.000
MatchedLengths "V_RX0PN MatchedLengths" [InNet('V_RX0N') Or  InNet('V_RX0P')] p1 off: tolerance=0.1 checknetsindiffpair=TRUE checkdiffpairvsdiffpair=TRUE checkothers=TRUE
MatchedLengths "RX0PN MatchedLengths" [InNet('RX0P') Or InNet('RX0N')] p2 off: tolerance=0.1 checknetsindiffpair=TRUE checkdiffpairvsdiffpair=TRUE checkothers=TRUE
PlaneClearance [All] p1: clearance=0.3
PlaneConnect PlaneConnect_Vias [IsVia] p1: planeconnectstyle=Direct reliefexpansion=0.5 reliefentries=4 reliefconductorwidth=0.25 reliefairgap=0.25
PlaneConnect [All] p2: planeconnectstyle=Relief reliefexpansion=0.5 reliefentries=4 reliefconductorwidth=0.25 reliefairgap=0.25
PolygonConnect [All] p1: connectstyle=Relief reliefconductorwidth=0.3 reliefentries=4 polygonreliefangle="90 Angle"
RoutingLayers [All] p1: top layer_v5=TRUE mid layer 1_v5=TRUE mid layer 2_v5=TRUE mid layer 3_v5=FALSE mid layer 4_v5=FALSE bottom layer_v5=TRUE
RoutingVias [All] p1: holewidth=0.3 width=0.6 viastyle="Through Hole" minholewidth=0.3 minwidth=0.5 maxholewidth=0.5 maxwidth=1
SMDNeckDown [All] p1: percent=100.000
SilkscreenOverComponentPads [All] p1: minsilkscreentomaskgap=0.254
SolderMaskExpansion [All] p1: expansion=0.15
Width "Rocket IO Width" [InNetClass('ROCKET_IO_LINES')] p1: maxlimit=0.279 minlimit=0.279 preferedwidth=0.279
Width [All] p2: maxlimit=5 minlimit=0.127 preferedwidth=0.2 toplayer_minwidth=0.2 midlayer4_prefwidth=0.127 bottomlayer_minwidth=0.2
18 further rules are at their usual default settings.

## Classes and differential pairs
component class "NBP8 Xilinx Virtex-II Pro BGA456 Rev1.01": C1 C2 C3 C4 C5 C6 C7 C8 C9 C10 C11 C12 C13 C14 C15 C16 C17 C18 C19 C20 C21 C22 C23 C24 C25 C26 C27 C28 C29 C30 C31 C32 C33 C34 C35 C36 C37 C38 C39 C40 C41 C42 C43 C44 C45 C46 C47 C48 C49 C50 C51 C52 C53 C54 C55 C56 C57 C58 HDR1 HDR2 LED1 LED2 R1 R2 R3 R4 R5 R6 R7 R8 R9 R10 R11 R12 R13 R14 R15 R16 R17 R18 R19 R20 TP1 TP2 TP3 TP4 TP5 TP6 TP7 TP8 TP9 TP10 TP11 TP13 TP14 U1 U2 U3 U4 U5
component class "Rocket Decoupling Caps": C68 C69 C70 C71 C72 C73 C74 C75
component class "Bottom Side": C1 C2 C3 C4 C5 C6 C7 C9 C10 C11 C12 C14 C15 C16 C17 C18 C19 C20 C21 C23 C24 C26 C28 C29 C34 C36 C37 C38 C39 C40 C41 C42 C43 C45 C47 C48 C49 C50 C54 C56 C57 C59 C66 C77 C80 C81 C82 C83 C84 C85 C86 C87 C89 C91 C92 C93 C94 HDR1 HDR2 L1 L2 L3 L4 L5 L6 L7 L8 L9 R1 R2 R3 R4 R5 R6 R7 R8 R9 R11 R12 R13 R22 R23 R24 R25 R26 R27 U7 U8
component class "Top Side": C8 C13 C22 C25 C27 C30 C31 C32 C33 C35 C44 C46 C51 C52 C53 C55 C58 C60 C61 C62 C63 C64 C65 C67 C68 C69 C70 C71 C72 C73 C74 C75 C76 C78 C79 C88 C90 LED1 LED2 P1 P2 P3 P4 P5 P6 P7 P8 R10 R14 R15 R16 R17 R18 R19 R20 R21 TP1 TP2 TP3 TP4 TP5 TP6 TP7 TP8 TP9 TP10 TP11 TP12 TP13 TP14 U1 U2 U3 U4 U5 U6
component class RIO_CONNECTORS: P1 P2 P3 P4 P5 P6 P7 P8
net class ROCKET_IO_LINES: RX0N RX0P RX1N RX1P TX0N TX0P TX1N TX1P V_RX0N V_RX0P V_RX1N V_RX1P V_TX0N V_TX0P V_TX1N V_TX1P
net class RX1: RX1N RX1P V_RX1N V_RX1P
net class TX1: TX1N TX1P V_TX1N V_TX1P
net class RX0: RX0N RX0P V_RX0N V_RX0P
net class TX0: TX0N TX0P V_TX0N V_TX0P
component class "PSU 1": C59 C60 C61 C62 C63 C64 C65 C66 C67 L1 R21 R22 R23 R24 R25 U6 U7
pad class 500andUp: U1-A8 U1-A9 U1-A14 U1-A15 U1-AA8 U1-AA9 U1-AA14 U1-AA15 U1-AB8 U1-AB9 U1-AB14 U1-B8 U1-B9 U1-B14 U1-B15 U1-C9 U1-C14 U1-C15 U1-D9 U1-D14 U1-D15 U1-E9 U1-F9 U1-J1 U1-J2 U1-J3 U1-J4 U1-J5 U1-J19 U1-J20 U1-J21 U1-J22 U1-K5 U1-K6 U1-K17 U1-K18 U1-K19 U1-K20 U1-L6 U1-N3 U1-N4 U1-N5 U1-N6 U1-N18 U1-N19 U1-N20 U1-P1 U1-P2 U1-P3 U1-P4 U1-P18 U1-P19 U1-P20 U1-P21 U1-P22 U1-U14 U1-V14 U1-W8 U1-W9 U1-W14 U1-Y8 U1-Y9 U1-Y14
pad class IN_ONLY: U1-A11 U1-AA11 U1-AA12 U1-C11 U1-D11 U1-D12 U1-F12 U1-F13 U1-W11 U1-W12 U1-Y11 U1-Y12
pad class IO: U1-A4 U1-A5 U1-A6 U1-A10 U1-A13 U1-A17 U1-A18 U1-A19 U1-AA5 U1-AA10 U1-AA13 U1-AA17 U1-AA18 U1-AA20 U1-AB5 U1-AB13 U1-AB16 U1-AB17 U1-AB18 U1-B4 U1-B5 U1-B6 U1-B10 U1-B12 U1-B13 U1-B17 U1-B18 U1-B19 U1-C1 U1-C2 U1-C4 U1-C6 U1-C10 U1-C12 U1-C13 U1-C18 U1-C21 U1-D1 U1-D2 U1-D6 U1-D10 U1-D13 U1-D17 U1-D18 U1-D21 U1-E1 U1-E2 U1-E3 U1-E4 U1-E5 U1-E6 U1-E7 U1-E8 U1-E10 U1-E11 U1-E13 U1-E14 U1-E16 U1-E17 U1-E18 U1-E19 U1-E20 U1-E21 U1-E22 U1-F10 U1-F11 U1-F18 U1-G1 U1-G2 U1-G21 U1-G22 U1-H1 U1-H2 U1-H3 U1-H4 U1-H5 U1-H19 U1-H20 U1-H21 U1-H22 U1-J6 U1-J17 U1-J18 U1-K1 U1-K2 U1-K3 U1-K4 U1-K21 U1-K22 U1-L2 U1-L3 U1-L4 U1-L5 U1-L17 U1-L18 U1-L19 U1-L20 U1-L21 U1-L22 U1-M1 U1-M2 U1-M3 U1-M4 U1-M5 U1-M6 U1-M17 U1-M18 U1-M19 U1-M20 U1-M21 U1-N1 U1-N2 U1-N17 U1-N21 U1-P5 U1-P6 U1-P17 U1-R1 U1-R2 U1-R3 U1-R4 U1-R18 U1-R19 U1-R20 U1-R21 U1-R22 U1-T1 U1-T2 U1-T21 U1-T22 U1-U3 U1-U4 U1-U10 U1-U11 U1-U12 U1-U13 U1-V3 U1-V4 U1-V5 U1-V6 U1-V7 U1-V9 U1-V10 U1-V12 U1-V13 U1-V19 U1-V20 U1-V21 U1-V22 U1-W1 U1-W2 U1-W6 U1-W10 U1-W13 U1-W17 U1-W21 U1-W22
pad class IO_CLK: U1-AB12 U1-B11 U1-E12 U1-V11
pad class PAR_DATA: U1-AA3 U1-AA4 U1-AB4 U1-AB19 U1-V17 U1-Y4 U1-Y5 U1-Y16 U1-Y18
pad class Fiducials: Free-FID
component class RIOP: C68 C69 C70 C71 C72 C73 C74 C75 C76 C77 C78 C79 C80 C81 C82 C83 C84 C85 C86 C87 C88 C89 C90 C91 C92 C93 C94 L2 L3 L4 L5 L6 L7 L8 L9 P1 P2 P3 P4 P5 P6 P7 P8 R26 R27 TP12 U8
differential pair D_TX1: +TX1P -TX1N
differential pair D_V_TX1: +V_TX1P -V_TX1N
differential pair D_RX1: +RX1P -RX1N
differential pair D_V_RX1: +V_RX1P -V_RX1N
differential pair D_V_RX0: +V_RX0P -V_RX0N
differential pair D_V_TX0: +V_TX0P -V_TX0N
differential pair D_DX: +DXP -DXN
differential pair D_RX0: +RX0P -RX0N
differential pair D_TX0: +TX0P -TX0N

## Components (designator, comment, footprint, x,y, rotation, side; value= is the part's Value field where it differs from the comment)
C1 "10nF" CC1608-0603 21,26 r270 bottom
C2 "10nF" CC1608-0603 41.5,25.5 r0 bottom
C3 "10nF" CC1608-0603 26,26 r270 bottom
C4 "10nF" CC1608-0603 16.5,49.5 r90 bottom
C5 "10nF" CC1608-0603 39.5,54.1 r90 bottom
C6 "10nF" CC1608-0603 32.5,26 r270 bottom
C7 "10nF" CC1608-0603 40,37 r270 bottom
C8 "10nF" CC1608-0603 2.5,6.5 r90 top
C9 "10nF" CC1608-0603 33.5,39 r180 bottom
C10 "10nF" CC1608-0603 29.5,43 r270 bottom
C11 "10nF" CC1608-0603 25.5,41 r0 bottom
C12 "10nF" CC1608-0603 29.5,37 r90 bottom
C13 "10nF" CC1608-0603 45.5,3 r0 top
C14 "10nF" CC1608-0603 25.5,39 r0 bottom
C15 "10nF" CC1608-0603 57.5,27 r0 bottom
C16 "10nF" CC1608-0603 33.5,41 r180 bottom
C17 "10nF" CC1608-0603 20.5,84.5 r90 bottom
C18 "10nF" CC1608-0603 31.5,44 r270 bottom
C19 "10nF" CC1608-0603 27.5,44 r270 bottom
C20 "10nF" CC1608-0603 31.5,36 r90 bottom
C21 "10nF" CC1608-0603 27.5,36 r90 bottom
C22 "10nF" CC1608-0603 48.7,56 r90 top
C23 "10nF" CC1608-0603 36.5,30 r180 bottom
C24 "10nF" CC1608-0603 24.5,34 r180 bottom
C25 "10nF" CC1608-0603 47,45.5 r270 top
C26 "10nF" CC1608-0603 4.5,49.5 r180 bottom
C27 "10nF" CC1608-0603 47.5,28 r180 top
C28 "220nF" CC1608-0603 52.5,3.5 r0 bottom
C29 "220nF" CC1608-0603 14,41.5 r180 bottom
C30 "220nF" CC1608-0603 21,26 r270 top
C31 "220nF" CC1608-0603 37.8,26.5 r180 top
C32 "220nF" CC1608-0603 4,9.5 r0 top
C33 "220nF" CC1608-0603 19,25 r270 top
C34 "220nF" CC1608-0603 14.5,49.5 r90 bottom
C35 "220nF" CC1608-0603 28.5,5 r90 top
C36 "10uF" MCCT-B 11,36 r180 bottom
C37 "10uF" MCCT-B 29,24.5 r270 bottom
C38 "10uF" MCCT-B 42.5,54 r90 bottom
C39 "10uF" MCCT-B 44,39 r0 bottom
C40 "10uF" MCCT-B 44,32 r270 bottom
C41 "10uF" MCCT-B 14,45.5 r180 bottom
C42 "10uF" MCCT-B 16.5,28.5 r270 bottom
C43 "10uF" MCCT-B 40.5,47.5 r90 bottom
C44 "10uF" MCCT-B 45,22.5 r270 top
C45 "10uF" MCCT-B 29,74 r270 bottom
C46 "10uF" MCCT-B 11,31.5 r270 top
C47 "10uF" MCCT-B 8,40 r180 bottom
C48 "10uF" MCCT-B 38,24.5 r270 bottom
C49 "10uF" MCCT-B 57.5,30.5 r0 bottom
C50 "10uF" MCCT-B 17,35.5 r180 bottom
C51 "220uF/4V" MCCT-D 13,26 r180 top
C52 "220uF/4V" MCCT-D 62.5,53.5 r270 top
C53 "220uF/4V" MCCT-D 37.6,17.9 r270 top
C54 "220uF/4V" MCCT-D 11.5,28.5 r270 bottom
C55 "220uF/4V" MCCT-D 54.5,56.3 r0 top
C56 "220uF/4V" MCCT-D 6,45.5 r180 bottom
C57 "220uF/4V" MCCT-D 62.5,23 r180 bottom
C58 "220uF/4V" MCCT-D 18,13.5 r0 top
C59 "10uF" MCCT-B 24,76 r270 bottom
C60 "10uF" MCCT-B 57.5,8 r90 top
C61 "100uF/6V/150mOhm" MCCT-D 54.5,51 r0 top
C62 "22uF/10V/Y5V" CC3225-1210 50,45 r90 top
C63 "22uF/10V/Y5V" CC3225-1210 55.5,46.5 r180 top
C64 "470pF" CC1608-0603 64,36 r90 top
C65 "2.2uF" CC3216-1206 66.5,35.5 r90 top
C66 "10uF/10V/1206/X7R" CC3216-1206 50.5,40.5 r270 bottom
C67 "1uF" CC3216-1206 66.5,41.5 r90 top
C68 "10nF" CC1005-0402 6.95,83 r90 top
C69 "10nF" CC1005-0402 8.25,83 r90 top
C70 "10nF" CC1005-0402 22.35,85 r90 top
C71 "10nF" CC1005-0402 23.65,85 r90 top
C72 "10nF" CC1005-0402 38.35,85.5 r90 top
C73 "10nF" CC1005-0402 39.65,85.5 r90 top
C74 "10nF" CC1005-0402 56.35,84 r90 top
C75 "10nF" CC1005-0402 57.65,84 r90 top
C76 "220nF" CC1608-0603 56.2,14.8 r270 top
C77 "220nF" CC1608-0603 20.5,54 r270 bottom
C78 "220nF" CC1608-0603 23.5,26 r270 top
C79 "220nF" CC1608-0603 35,26 r270 top
C80 "220nF" CC1608-0603 24.5,51.5 r270 bottom
C81 "220nF" CC1608-0603 22.5,51.5 r270 bottom
C82 "220nF" CC1608-0603 26.5,51.5 r270 bottom
C83 "220nF" CC1608-0603 28.5,51.5 r270 bottom
C84 "220nF" CC1608-0603 36.5,51.5 r270 bottom
C85 "220nF" CC1608-0603 34.5,51.5 r270 bottom
C86 "220nF" CC1608-0603 30.5,51.5 r270 bottom
C87 "220nF" CC1608-0603 32.5,51.5 r270 bottom
C88 "10uF" MCCT-B 66,15 r270 top
C89 "10uF" MCCT-B 17.5,54.5 r270 bottom
C90 "10uF" MCCT-B 49.5,65.5 r0 top
C91 "220uF/4V" MCCT-D 7,53.5 r180 bottom
C92 "10uF/10V/1206/X7R" CC3216-1206 49.5,77 r270 bottom
C93 "10uF/10V/1206/X7R" CC3216-1206 59,72 r90 bottom
C94 "10nF NPO" CC3216-1206 59.5,81.5 r0 bottom
HDR1 "54075-1009-HD1" 54075 34.5,63.9 r0 bottom locked
HDR2 "54075-1009-HD2" 54075 34.5,13.1 r0 bottom locked
L1 "SB1806/2R2MS" "IND SB1806" 57,50 r180 bottom
L2 "Inductor" CC1608-0603 22.5,55.5 r90 bottom
L3 "Inductor" CC1608-0603 24.5,55.5 r90 bottom
L4 "Inductor" CC1608-0603 28.5,55.5 r90 bottom
L5 "Inductor" CC1608-0603 26.5,55.5 r90 bottom
L6 "Inductor" CC1608-0603 30.5,55.5 r90 bottom
L7 "Inductor" CC1608-0603 32.5,55.5 r90 bottom
L8 "Inductor" CC1608-0603 36.5,55.5 r90 bottom
L9 "Inductor" CC1608-0603 34.5,55.5 r90 bottom
LED1 "HSMH-C170" "SMD _LED" 49.5,5.5 r180 top locked
LED2 "HSMG-C170" "SMD _LED" 19.5,5.5 r180 top locked
P1 "SMB" SMB_V-RJ45 4.5,90.5 r0 top
P2 "SMB" SMB_V-RJ45 14,87.5 r0 top
P3 "SMB" SMB_V-RJ45 22,93.5 r0 top
P4 "SMB" SMB_V-RJ45 30.5,88.5 r0 top
P5 "SMB" SMB_V-RJ45 39,94 r0 top
P6 "SMB" SMB_V-RJ45 47,88 r0 top
P7 "SMB" SMB_V-RJ45 56,92.5 r0 top
P8 "SMB" SMB_V-RJ45 64.5,87 r0 top
R1 "100R" CC2012-0805 32.5,76 r270 bottom
R2 "100R" CC2012-0805 35,73 r270 bottom
R3 "100R" CC2012-0805 35.5,77 r270 bottom
R4 "100R" CC2012-0805 43.5,72 r270 bottom
R5 "100R" CC2012-0805 45.5,76 r270 bottom
R6 "100R" CC2012-0805 48.5,72 r270 bottom
R7 "100R" CC2012-0805 40.5,72 r90 bottom
R8 "100R" CC2012-0805 38,73 r90 bottom
R9 "100R" CC2012-0805 32,72 r270 bottom
R10 "100R" CC2012-0805 15.5,5.5 r180 top
R11 "470R" CC2012-0805 38,77 r90 bottom
R12 "470R" CC2012-0805 29.45,82 r0 bottom
R13 "470R" CC2012-0805 40.7,76.5 r270 bottom
R14 "470R" CC2012-0805 29,2.1 r0 top
R15 "82R1%" CC2012-0805 55.05,61.5 r180 top
R16 "680R1%" CC2012-0805 55.1,64.1 r0 top
R17 "100k" CC2012-0805 15.5,2.5 r180 top
R18 "1M" CC2012-0805 2.5,3 r90 top
R19 "270R" CC2012-0805 45.5,5.5 r180 top
R20 "270R" CC2012-0805 19.5,2.5 r180 top
R21 "10R" CC2012-0805 53.5,41 r180 top
R22 "82k" CC2012-0805 60,38.5 r180 bottom
R23 "560R1%" CC2012-0805 24,85.5 r180 bottom
R24 "220R1%" CC2012-0805 24.05,83 r180 bottom
R25 "220R1%" CC2012-0805 24,80.5 r0 bottom
R26 "470R" CC2012-0805 50,81.5 r180 bottom
R27 "100k" CC2012-0805 53.5,82.5 r90 bottom
TP1 "(CCLK)" TestPin 40.5,69.5 r90 top
TP2 "(ProgB)" TestPin 40,80 r180 top
TP3 "(TDI)" TestPin 47,79 r90 top
TP4 "(TDO)" TestPin 31.5,79 r180 top
TP5 "(TCK)" TestPin 43.5,76.5 r180 top
TP6 "(TMS)" TestPin 42,79.5 r180 top
TP7 "(5V)" TestPin 53.5,5.5 r90 top
TP8 "(RefClk)" TestPin 15.5,21 r90 top
TP9 "(FpgaClk)" TestPin 15,19 r90 top
TP10 "(1.5V)" TestPin 49,53.5 r90 top
TP11 "(3V)" TestPin 59.5,4 r90 top
TP12 "(2.5VRIO)" TestPin 7.5,29.5 r90 top
TP13 "(3.3V)" TestPin 65.8,19.8 r90 top
TP14 "(2.5V)" TestPin 50,2 r90 top
U1 "XC2VP4-5FG456C" FG456 29.5,40 r180 top
U2 "MAX1617DBR2" QSOP16 9,5 r270 top
U3 "SRAM 512Kx16 TSOP44" SO-G44/P.8 8.8,47 r270 top
U4 "SRAM 512Kx16 TSOP44" SO-G44/P.8 56,28 r270 top
U5 "SN74LVC1G04DBV" SO-G5/P.95 24.5,5.5 r90 top
U6 "MAX1831EEE" QSOP16_150_25 60,41.5 r0 top
U7 "LM1084IS-ADJ" TO-263 18.5,79.04 r270 bottom
U8 "LP2989IM-2.5" SO-8 55.5,77 r270 bottom

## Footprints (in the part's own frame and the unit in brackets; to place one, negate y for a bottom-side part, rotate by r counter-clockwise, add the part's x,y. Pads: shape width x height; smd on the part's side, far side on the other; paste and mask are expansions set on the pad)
54075 [mm] "Connector; Docking Station, Receptacle; 100 Position; Vertical"
  rect 0.5x1.9 smd: 1(-19.6,3.4) 2(-19.6,-3.4) 3(-18.8,3.4) 4(-18.8,-3.4) 5(-18,3.4) 6(-18,-3.4) 7(-17.2,3.4) 8(-17.2,-3.4) 9(-16.4,3.4) 10(-16.4,-3.4) 11(-15.6,3.4) 12(-15.6,-3.4) 13(-14.8,3.4) 14(-14.8,-3.4) 15(-14,3.4) 16(-14,-3.4) 17(-13.2,3.4) 18(-13.2,-3.4) 19(-12.4,3.4) 20(-12.4,-3.4) 21(-11.6,3.4) 22(-11.6,-3.4) 23(-10.8,3.4) 24(-10.8,-3.4) 25(-10,3.4) 26(-10,-3.4) 27(-9.2,3.4) 28(-9.2,-3.4) 29(-8.4,3.4) 30(-8.4,-3.4) 31(-7.6,3.4) 32(-7.6,-3.4) 33(-6.8,3.4) 34(-6.8,-3.4) 35(-6,3.4) 36(-6,-3.4) 37(-5.2,3.4) 38(-5.2,-3.4) 39(-4.4,3.4) 40(-4.4,-3.4) 41(-3.6,3.4) 42(-3.6,-3.4) 43(-2.8,3.4) 44(-2.8,-3.4) 45(-2,3.4) 46(-2,-3.4) 47(-1.2,3.4) 48(-1.2,-3.4) 49(-0.4,3.4) 50(-0.4,-3.4) 51(0.4,3.4) 52(0.4,-3.4) 53(1.2,3.4) 54(1.2,-3.4) 55(2,3.4) 56(2,-3.4) 57(2.8,3.4) 58(2.8,-3.4) 59(3.6,3.4) 60(3.6,-3.4) 61(4.4,3.4) 62(4.4,-3.4) 63(5.2,3.4) 64(5.2,-3.4) 65(6,3.4) 66(6,-3.4) 67(6.8,3.4) 68(6.8,-3.4) 69(7.6,3.4) 70(7.6,-3.4) 71(8.4,3.4) 72(8.4,-3.4) 73(9.2,3.4) 74(9.2,-3.4) 75(10,3.4) 76(10,-3.4) 77(10.8,3.4) 78(10.8,-3.4) 79(11.6,3.4) 80(11.6,-3.4) 81(12.4,3.4) 82(12.4,-3.4) 83(13.2,3.4) 84(13.2,-3.4) 85(14,3.4) 86(14,-3.4) 87(14.8,3.4) 88(14.8,-3.4) 89(15.6,3.4) 90(15.6,-3.4) 91(16.4,3.4) 92(16.4,-3.4) 93(17.2,3.4) 94(17.2,-3.4) 95(18,3.4) 96(18,-3.4) 97(18.8,3.4) 98(18.8,-3.4) 99(19.6,3.4) 100(19.6,-3.4)
  round 0.5 hole 0.7 unplated: MH1(-26.7,4.2) MH2(-25.9,-4.2) MH3(26.7,4.2) MH4(25.9,-4.2)
  round 4.8 hole 5.1 unplated: MH5(-26.3,0) MH6(26.3,0)
  Top Layer keep-out region: -20.15,2.15 20.15,2.15 20.15,-2.15 -20.15,-2.15
  silkscreen extent -30.35,-4.4 30.35,5.02
CC1005-0402 [mm]
  rect 0.9x0.7 smd: 1(-0.65,0) 2(0.65,0)
  silkscreen extent -0.55,-0.6 0.55,0.6
CC1608-0603 [mm]
  rect 1.1x1 smd: 1(-0.85,0) 2(0.85,0)
  silkscreen extent -0.85,-0.75 0.85,0.75
CC2012-0805 [mm]
  rect 1.3x1.5 smd: 1(-0.95,0) 2(0.95,0)
  silkscreen extent -1.1,-1 1.1,1
CC3216-1206 [mm]
  rect 1.6x1.8 smd: 1(-1.4,0) 2(1.4,0)
  silkscreen extent -1.7,-1.15 1.7,1.15
CC3225-1210 [mm]
  rect 1.6x2.7 smd: 1(-1.4,0) 2(1.4,0)
  silkscreen extent -1.7,-1.6 1.7,1.6
FG456 [mm] "456-Ball Fine Pitch Ball Grid Array (FG456)"
  round 0.4 smd mask+0.2: A1(-10.5,10.5) A2(-9.5,10.5) A3(-8.5,10.5) A4(-7.5,10.5) A5(-6.5,10.5) A6(-5.5,10.5) A7(-4.5,10.5) A8(-3.5,10.5) A9(-2.5,10.5) A10(-1.5,10.5) A11(-0.5,10.5) A12(0.5,10.5) A13(1.5,10.5) A14(2.5,10.5) A15(3.5,10.5) A16(4.5,10.5) A17(5.5,10.5) A18(6.5,10.5) A19(7.5,10.5) A20(8.5,10.5) A21(9.5,10.5) A22(10.5,10.5) AA1(-10.5,-9.5) AA2(-9.5,-9.5) AA3(-8.5,-9.5) AA4(-7.5,-9.5) AA5(-6.5,-9.5) AA6(-5.5,-9.5) AA7(-4.5,-9.5) AA8(-3.5,-9.5) AA9(-2.5,-9.5) AA10(-1.5,-9.5) AA11(-0.5,-9.5) AA12(0.5,-9.5) AA13(1.5,-9.5) AA14(2.5,-9.5) AA15(3.5,-9.5) AA16(4.5,-9.5) AA17(5.5,-9.5) AA18(6.5,-9.5) AA19(7.5,-9.5) AA20(8.5,-9.5) AA21(9.5,-9.5) AA22(10.5,-9.5) AB1(-10.5,-10.5) AB2(-9.5,-10.5) AB3(-8.5,-10.5) AB4(-7.5,-10.5) AB5(-6.5,-10.5) AB6(-5.5,-10.5) AB7(-4.5,-10.5) AB8(-3.5,-10.5) AB9(-2.5,-10.5) AB10(-1.5,-10.5) AB11(-0.5,-10.5) AB12(0.5,-10.5) AB13(1.5,-10.5) AB14(2.5,-10.5) AB15(3.5,-10.5) AB16(4.5,-10.5) AB17(5.5,-10.5) AB18(6.5,-10.5) AB19(7.5,-10.5) AB20(8.5,-10.5) AB21(9.5,-10.5) AB22(10.5,-10.5) B1(-10.5,9.5) B2(-9.5,9.5) B3(-8.5,9.5) B4(-7.5,9.5) B5(-6.5,9.5) B6(-5.5,9.5) B7(-4.5,9.5) B8(-3.5,9.5) B9(-2.5,9.5) B10(-1.5,9.5) B11(-0.5,9.5) B12(0.5,9.5) B13(1.5,9.5) B14(2.5,9.5) B15(3.5,9.5) B16(4.5,9.5) B17(5.5,9.5) B18(6.5,9.5) B19(7.5,9.5) B20(8.5,9.5) B21(9.5,9.5) B22(10.5,9.5) C1(-10.5,8.5) C2(-9.5,8.5) C3(-8.5,8.5) C4(-7.5,8.5) C5(-6.5,8.5) C6(-5.5,8.5) C7(-4.5,8.5) C8(-3.5,8.5) C9(-2.5,8.5) C10(-1.5,8.5) C11(-0.5,8.5) C12(0.5,8.5) C13(1.5,8.5) C14(2.5,8.5) C15(3.5,8.5) C16(4.5,8.5) C17(5.5,8.5) C18(6.5,8.5) C19(7.5,8.5) C20(8.5,8.5) C21(9.5,8.5) C22(10.5,8.5) D1(-10.5,7.5) D2(-9.5,7.5) D3(-8.5,7.5) D4(-7.5,7.5) D5(-6.5,7.5) D6(-5.5,7.5) D7(-4.5,7.5) D8(-3.5,7.5) D9(-2.5,7.5) D10(-1.5,7.5) D11(-0.5,7.5) D12(0.5,7.5) D13(1.5,7.5) D14(2.5,7.5) D15(3.5,7.5) D16(4.5,7.5) D17(5.5,7.5) D18(6.5,7.5) D19(7.5,7.5) D20(8.5,7.5) D21(9.5,7.5) D22(10.5,7.5) E1(-10.5,6.5) E2(-9.5,6.5) E3(-8.5,6.5) E4(-7.5,6.5) E5(-6.5,6.5) E6(-5.5,6.5) E7(-4.5,6.5) E8(-3.5,6.5) E9(-2.5,6.5) E10(-1.5,6.5) E11(-0.5,6.5) E12(0.5,6.5) E13(1.5,6.5) E14(2.5,6.5) E15(3.5,6.5) E16(4.5,6.5) E17(5.5,6.5) E18(6.5,6.5) E19(7.5,6.5) E20(8.5,6.5) E21(9.5,6.5) E22(10.5,6.5) F1(-10.5,5.5) F2(-9.5,5.5) F3(-8.5,5.5) F4(-7.5,5.5) F5(-6.5,5.5) F6(-5.5,5.5) F7(-4.5,5.5) F8(-3.5,5.5) F9(-2.5,5.5) F10(-1.5,5.5) F11(-0.5,5.5) F12(0.5,5.5) F13(1.5,5.5) F14(2.5,5.5) F15(3.5,5.5) F16(4.5,5.5) F17(5.5,5.5) F18(6.5,5.5) F19(7.5,5.5) F20(8.5,5.5) F21(9.5,5.5) F22(10.5,5.5) G1(-10.5,4.5) G2(-9.5,4.5) G3(-8.5,4.5) G4(-7.5,4.5) G5(-6.5,4.5) G6(-5.5,4.5) G7(-4.5,4.5) G8(-3.5,4.5) G9(-2.5,4.5) G10(-1.5,4.5) G11(-0.5,4.5) G12(0.5,4.5) G13(1.5,4.5) G14(2.5,4.5) G15(3.5,4.5) G16(4.5,4.5) G17(5.5,4.5) G18(6.5,4.5) G19(7.5,4.5) G20(8.5,4.5) G21(9.5,4.5) G22(10.5,4.5) H1(-10.5,3.5) H2(-9.5,3.5) H3(-8.5,3.5) H4(-7.5,3.5) H5(-6.5,3.5) H6(-5.5,3.5) H7(-4.5,3.5) H16(4.5,3.5) H17(5.5,3.5) H18(6.5,3.5) H19(7.5,3.5) H20(8.5,3.5) H21(9.5,3.5) H22(10.5,3.5) J1(-10.5,2.5) J2(-9.5,2.5) J3(-8.5,2.5) J4(-7.5,2.5) J5(-6.5,2.5) J6(-5.5,2.5) J7(-4.5,2.5) J9(-2.5,2.5) J10(-1.5,2.5) J11(-0.5,2.5) J12(0.5,2.5) J13(1.5,2.5) J14(2.5,2.5) J16(4.5,2.5) J17(5.5,2.5) J18(6.5,2.5) J19(7.5,2.5) J20(8.5,2.5) J21(9.5,2.5) J22(10.5,2.5) K1(-10.5,1.5) K2(-9.5,1.5) K3(-8.5,1.5) K4(-7.5,1.5) K5(-6.5,1.5) K6(-5.5,1.5) K7(-4.5,1.5) K9(-2.5,1.5) K10(-1.5,1.5) K11(-0.5,1.5) K12(0.5,1.5) K13(1.5,1.5) K14(2.5,1.5) K16(4.5,1.5) K17(5.5,1.5) K18(6.5,1.5) K19(7.5,1.5) K20(8.5,1.5) K21(9.5,1.5) K22(10.5,1.5) L1(-10.5,0.5) L2(-9.5,0.5) L3(-8.5,0.5) L4(-7.5,0.5) L5(-6.5,0.5) L6(-5.5,0.5) L7(-4.5,0.5) L9(-2.5,0.5) L10(-1.5,0.5) L11(-0.5,0.5) L12(0.5,0.5) L13(1.5,0.5) L14(2.5,0.5) L16(4.5,0.5) L17(5.5,0.5) L18(6.5,0.5) L19(7.5,0.5) L20(8.5,0.5) L21(9.5,0.5) L22(10.5,0.5) M1(-10.5,-0.5) M2(-9.5,-0.5) M3(-8.5,-0.5) M4(-7.5,-0.5) M5(-6.5,-0.5) M6(-5.5,-0.5) M7(-4.5,-0.5) M9(-2.5,-0.5) M10(-1.5,-0.5) M11(-0.5,-0.5) M12(0.5,-0.5) M13(1.5,-0.5) M14(2.5,-0.5) M16(4.5,-0.5) M17(5.5,-0.5) M18(6.5,-0.5) M19(7.5,-0.5) M20(8.5,-0.5) M21(9.5,-0.5) M22(10.5,-0.5) N1(-10.5,-1.5) N2(-9.5,-1.5) N3(-8.5,-1.5) N4(-7.5,-1.5) N5(-6.5,-1.5) N6(-5.5,-1.5) N7(-4.5,-1.5) N9(-2.5,-1.5) N10(-1.5,-1.5) N11(-0.5,-1.5) N12(0.5,-1.5) N13(1.5,-1.5) N14(2.5,-1.5) N16(4.5,-1.5) N17(5.5,-1.5) N18(6.5,-1.5) N19(7.5,-1.5) N20(8.5,-1.5) N21(9.5,-1.5) N22(10.5,-1.5) P1(-10.5,-2.5) P2(-9.5,-2.5) P3(-8.5,-2.5) P4(-7.5,-2.5) P5(-6.5,-2.5) P6(-5.5,-2.5) P7(-4.5,-2.5) P9(-2.5,-2.5) P10(-1.5,-2.5) P11(-0.5,-2.5) P12(0.5,-2.5) P13(1.5,-2.5) P14(2.5,-2.5) P16(4.5,-2.5) P17(5.5,-2.5) P18(6.5,-2.5) P19(7.5,-2.5) P20(8.5,-2.5) P21(9.5,-2.5) P22(10.5,-2.5) R1(-10.5,-3.5) R2(-9.5,-3.5) R3(-8.5,-3.5) R4(-7.5,-3.5) R5(-6.5,-3.5) R6(-5.5,-3.5) R7(-4.5,-3.5) R16(4.5,-3.5) R17(5.5,-3.5) R18(6.5,-3.5) R19(7.5,-3.5) R20(8.5,-3.5) R21(9.5,-3.5) R22(10.5,-3.5) T1(-10.5,-4.5) T2(-9.5,-4.5) T3(-8.5,-4.5) T4(-7.5,-4.5) T5(-6.5,-4.5) T6(-5.5,-4.5) T7(-4.5,-4.5) T8(-3.5,-4.5) T9(-2.5,-4.5) T10(-1.5,-4.5) T11(-0.5,-4.5) T12(0.5,-4.5) T13(1.5,-4.5) T14(2.5,-4.5) T15(3.5,-4.5) T16(4.5,-4.5) T17(5.5,-4.5) T18(6.5,-4.5) T19(7.5,-4.5) T20(8.5,-4.5) T21(9.5,-4.5) T22(10.5,-4.5) U1(-10.5,-5.5) U2(-9.5,-5.5) U3(-8.5,-5.5) U4(-7.5,-5.5) U5(-6.5,-5.5) U6(-5.5,-5.5) U7(-4.5,-5.5) U8(-3.5,-5.5) U9(-2.5,-5.5) U10(-1.5,-5.5) U11(-0.5,-5.5) U12(0.5,-5.5) U13(1.5,-5.5) U14(2.5,-5.5) U15(3.5,-5.5) U16(4.5,-5.5) U17(5.5,-5.5) U18(6.5,-5.5) U19(7.5,-5.5) U20(8.5,-5.5) U21(9.5,-5.5) U22(10.5,-5.5) V1(-10.5,-6.5) V2(-9.5,-6.5) V3(-8.5,-6.5) V4(-7.5,-6.5) V5(-6.5,-6.5) V6(-5.5,-6.5) V7(-4.5,-6.5) V8(-3.5,-6.5) V9(-2.5,-6.5) V10(-1.5,-6.5) V11(-0.5,-6.5) V12(0.5,-6.5) V13(1.5,-6.5) V14(2.5,-6.5) V15(3.5,-6.5) V16(4.5,-6.5) V17(5.5,-6.5) V18(6.5,-6.5) V19(7.5,-6.5) V20(8.5,-6.5) V21(9.5,-6.5) V22(10.5,-6.5) W1(-10.5,-7.5) W2(-9.5,-7.5) W3(-8.5,-7.5) W4(-7.5,-7.5) W5(-6.5,-7.5) W6(-5.5,-7.5) W7(-4.5,-7.5) W8(-3.5,-7.5) W9(-2.5,-7.5) W10(-1.5,-7.5) W11(-0.5,-7.5) W12(0.5,-7.5) W13(1.5,-7.5) W14(2.5,-7.5) W15(3.5,-7.5) W16(4.5,-7.5) W17(5.5,-7.5) W18(6.5,-7.5) W19(7.5,-7.5) W20(8.5,-7.5) W21(9.5,-7.5) W22(10.5,-7.5) Y1(-10.5,-8.5) Y2(-9.5,-8.5) Y3(-8.5,-8.5) Y4(-7.5,-8.5) Y5(-6.5,-8.5) Y6(-5.5,-8.5) Y7(-4.5,-8.5) Y8(-3.5,-8.5) Y9(-2.5,-8.5) Y10(-1.5,-8.5) Y11(-0.5,-8.5) Y12(0.5,-8.5) Y13(1.5,-8.5) Y14(2.5,-8.5) Y15(3.5,-8.5) Y16(4.5,-8.5) Y17(5.5,-8.5) Y18(6.5,-8.5) Y19(7.5,-8.5) Y20(8.5,-8.5) Y21(9.5,-8.5) Y22(10.5,-8.5)
  silkscreen extent -12.28,-11.5 11.5,11.5
"IND SB1806" [mm] "ABC Electronics"
  rect 5x4 smd: 1(-8,0) 2(8,0)
  silkscreen extent -8.5,-7 8.5,7
MCCT-B [mm]
  rect 2x2.2 smd: 1(-1.5,0) 2(1.5,0)
  silkscreen extent -2.3,-1.6 1.8,1.6
MCCT-D [mm]
  rect 2.6x2.4 smd: 1(-3.2,0) 2(3.2,0)
  silkscreen extent -4.2,-2.4 3.7,2.4
QSOP16 [mm] "SSOP; 16 Leads; Body Width 3.9 mm; Pitch 0.635 mm"
  rect 0.4x2.2 smd: 1(-2.222,-2.6) 2(-1.587,-2.6) 3(-0.952,-2.6) 4(-0.317,-2.6) 5(0.318,-2.6) 6(0.953,-2.6) 7(1.588,-2.6) 8(2.223,-2.6) 9(2.222,2.6) 10(1.587,2.6) 11(0.952,2.6) 12(0.317,2.6) 13(-0.318,2.6) 14(-0.953,2.6) 15(-1.588,2.6) 16(-2.223,2.6)
  silkscreen extent -3.1,-2.72 2.5,1.1
QSOP16_150_25 [mil]
  rect 70x15 smd: 1(-117.5,87.5)
  oval 70x15 smd: 2(-117.5,62.5) 3(-117.5,37.5) 4(-117.5,12.5) 5(-117.5,-12.5) 6(-117.5,-37.5) 7(-117.5,-62.5) 8(-117.5,-87.5) 9(117.5,-87.5) 10(117.5,-62.5) 11(117.5,-37.5) 12(117.5,-12.5) 13(117.5,12.5) 14(117.5,37.5) 15(117.5,62.5) 16(117.5,87.5)
  silkscreen extent -74,-100 74,100
SMB_V-RJ45 [mm] "Connector; SMB Straight"
  round 2.5 hole 1.5: 1(0,0) 2(-2.5,-2.5) 2(-2.5,2.5) 2(2.5,-2.5) 2(2.5,2.5)
  silkscreen extent -3.15,-3.15 3.15,3.15
"SMD _LED" [mm]
  rect 1.3x1.6 smd: 1(0.95,0) 2(-0.95,0)
  silkscreen extent -2.13,-1.15 2,1.15
SO-8 [mm] "Small Outline; 8 Leads; Body Width 3.9 mm; Pitch 1.27 mm"
  rect 0.6x2.2 smd: 1(-1.905,-2.6) 2(-0.635,-2.6) 3(0.635,-2.6) 4(1.905,-2.6) 5(1.905,2.6) 6(0.635,2.6) 7(-0.635,2.6) 8(-1.905,2.6)
  silkscreen extent -2.88,-2.72 2.5,1.1
SO-G5/P.95 [mm]
  rect 0.55x1.45 smd: 1(-0.959,-1.07) 2(-0.009,-1.07) 3(0.941,-1.07) 4(0.941,1.08) 5(-0.959,1.08)
  silkscreen extent -2.43,-2.19 1.64,2.21
SO-G44/P.8 [mm]
  rect 0.45x1.45 smd: 1(-8.4,-5.575) 2(-7.6,-5.575) 3(-6.8,-5.575) 4(-6,-5.575) 5(-5.2,-5.575) 6(-4.4,-5.575) 7(-3.6,-5.575) 8(-2.8,-5.575) 9(-2,-5.575) 10(-1.2,-5.575) 11(-0.4,-5.575) 12(0.4,-5.575) 13(1.2,-5.575) 14(2,-5.575) 15(2.8,-5.575) 16(3.6,-5.575) 17(4.4,-5.575) 18(5.2,-5.575) 19(6,-5.575) 20(6.8,-5.575) 21(7.6,-5.575) 22(8.4,-5.575) 23(8.4,5.575) 24(7.6,5.575) 25(6.8,5.575) 26(6,5.575) 27(5.2,5.575) 28(4.4,5.575) 29(3.6,5.575) 30(2.8,5.575) 31(2,5.575) 32(1.2,5.575) 33(0.4,5.575) 34(-0.4,5.575) 35(-1.2,5.575) 36(-2,5.575) 37(-2.8,5.575) 38(-3.6,5.575) 39(-4.4,5.575) 40(-5.2,5.575) 41(-6,5.575) 42(-6.8,5.575) 43(-7.6,5.575) 44(-8.4,5.575)
  silkscreen extent -9.3,-5.7 9.25,4.45
TestPin [mil] "SingleTest Pin"
  round 60 hole 35.43: 1(0,0)
TO-263 [mm]
  rect 1x4.5 smd: 1(0,0) 2(2.54,0) 3(5.08,0)
  rect 10.25x8.9 smd: 4(2.54,10.45)
  silkscreen extent -3.1,-3.13 8.2,15

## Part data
C1 C2 C3 C4 C5 C6 C7 C8 C9 C10 C11 C12 C13 C14 C15 C16 C17 C18 C19 C20 C21 C22 C23 C24 C25 C26 C27 C28 C29 C30 C31 C32 C33 C34 C35 C62 C63 C64 C65 C66 C67 C68 C69 C70 C71 C72 C73 C74 C75 C76 C77 C78 C79 C80 C81 C82 C83 C84 C85 C86 C87 C92 C93 C94: library part CAP, "Capacitor"
C36 C37 C38 C39 C40 C41 C42 C43 C44 C45 C46 C47 C48 C49 C50 C51 C52 C53 C54 C55 C56 C57 C58 C59 C60 C61 C88 C89 C90 C91: library part CAP_POLAR, "Polar Capacitor"
HDR1 HDR2: "Board-to-Board, Docking Station, 0.80mm (.031\") Pitch, Shielded Receptacle, Vertical, Ultra Low Profile, SMT"
L1: library part "Inductor Iron Dot", "Magnetic-Core Inductor with Winding Polarity Marking"
LED1: library part HSMX-C670, "Typical RED GaAs SMD LED Agilent make"
LED2: library part HSMX-C670, "Typical GREEN GaAs SMD LED Agilent make"
P1 P2 P3 P4 P5 P6 P7 P8: "SMB Straight Connector"
R1 R2 R3 R4 R5 R6 R7 R8 R9 R10 R11 R12 R13 R14 R15 R16 R17 R18 R19 R20 R21 R22 R23 R24 R25 R26 R27: library part RES, "Resistor"
TP1 TP2 TP3 TP4 TP5 TP6 TP7 TP8 TP9 TP10 TP11 TP12 TP13 TP14: library part TestPin
U1: "Virtex-II Pro Platform FPGA, 456-Ball FBGA, Speed Grade 5, 248 User I/Os, Commercial Grade"
U2: "SMBus Temperature Sensor with Internal and External Diode Input"
U3 U4: "512Kx16Bit SRAM TSOP44"
U5: library part SN74AHC1G04DBVR
U6: "3A,!MHz, Low Voltage, Step-Down Regulator with Synchronous Rectification and Internal Switches"
U7: "5A Low Dropout Positive Regulators"
U8: library part LP2989, "NS Micropower/Low Noise 500mA LDO"

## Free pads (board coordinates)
  round 1 smd mask+2: FID(4.3,21.3) FID(22.1,64.5) FID(50.7,12.6)
  round 1 smd far side mask+2: FID(8.9,20.8) FID(39.2,85.6) FID(56.1,35.1)
  round 3.2 hole 3.5 unplated: LP(4,34) LP(65,4) LP(65,73)

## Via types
v1: diameter 0.6, hole 0.3, Top Layer to Bottom Layer, tented bottom, 695 vias
v2: diameter 0.9, hole 0.5, Top Layer to Bottom Layer, tented bottom, 45 vias
v3: diameter 1.8, hole 1, Top Layer to Bottom Layer, tented bottom, 26 vias
v4: diameter 1, hole 0.7, Top Layer to Bottom Layer, tented bottom, 17 vias
v5: diameter 1, hole 0.5, Top Layer to Bottom Layer, tented bottom, 15 vias
v6: diameter 1.5, hole 1, Top Layer to Bottom Layer, tented bottom, 4 vias
v7: diameter 0.8, hole 0.4, Top Layer to Bottom Layer, tented bottom, 3 vias
v8: diameter 0.9, hole 0.5, Top Layer to Bottom Layer, 2 vias

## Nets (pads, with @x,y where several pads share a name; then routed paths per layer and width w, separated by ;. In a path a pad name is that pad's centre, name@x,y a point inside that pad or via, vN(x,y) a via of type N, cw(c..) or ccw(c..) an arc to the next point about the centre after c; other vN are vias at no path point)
5V: C59.1 C63.2 C66.2 HDR1.97 HDR1.99 HDR2.97 HDR2.99 R21.2 TP7.1 U6.2 U6.4 U7.3 | length 203.7
  Top Layer w0.38: R21.2@52.55,41 52.55,41.75 v5@53.6,42.8 ; 54.412,43.088 55,43.088 55.1,43.088 U6.2@57.015,43.088 ; 55.2,42.4 55.782,41.818 U6.4@57.015,41.818
  Top Layer w0.4: v1(51.2,40.5) 52.05,40.5 R21.2@52.55,41
  Top Layer w1.5: 54.1,58.3 54.1,54.9 55,54 55,46.5 55,44.1 55,43.088 v5@55,42.9
  MidLayer1 w1.5: v5(26.5,78.7) v5(27.6,78.7) v5(28.7,78.7) 29.5,79.5 29.5,80.5 31.2,82.2 43.7,82.2 44.4,81.5 48,81.5 51.8,77.7 51.8,70.5 52.1,70.1 52.1,65.2 54.1,63.2 v2(54.1,58.9) 54.1,58.4 53.9,58.2 54.1,58.2 54.3,58.2 54.4,58.1 55.2,57.3 55.2,48 54.3,47.1 54.3,44.1 54.3,43.8 54.4,43.7 54.4,42.9 54.4,38.3 56,36.7 56,30.3 58.1,28.2 58.1,22 55.9,19.8 55.9,8.1 53.5,5.7 TP7.1@53.5,5.5
  Bottom Layer w0.4: C66.2@50.5,39.1 C66.2@50.5,39.2 ; v1(51.2,40.5) 52.6,40.5 ; HDR2.97@53.3,9.7 53.3,5.7 TP7.1@53.5,5.5 ; 54.2,7.7 HDR2.99@54.2,9.7
  Bottom Layer w0.5: 53.3,59.1 HDR1.97@53.3,60.5 ; v2@54.1,59.1 HDR1.99@54.1,60.5
  Bottom Layer w1: U7.3@18.5,73.96 20.9,74 21.8,74.9 21.8,76.5 22.8,77.5 C59.1@24,77.5 ; C59.1@24.1,77.5 24.9,77.5 26.1,78.7 v5(26.5,78.7) v5(27.6,78.7) v5(28.7,78.7) v5@28.8,78.7 ; C66.2@50.5,39.2 52.5,39.2 ; TP7.1@53.5,5.5 53.5,7.7 54.2,7.7 55.1,7.7 56,8.6 56,20.7 53.6,23.1 53.6,26.9 53,27.5 53,31.1 52.1,32 52.1,37.5 52.6,38 52.6,40.5 52.6,41.2 ; v5@54,42.6 52.6,41.2 ; v5@55.3,44.1 v5(55.1,44.1) v5(53.9,44.1) 53.1,44.1 52.6,43.6 52.6,41.2
  other v2: 53.6,58.3 54.6,58.3
  other v5: 53.9,42.9 55.1,42.9
AUDIO_SPI_CSN: HDR1.11 U1.AB21 | length 10.5
  Top Layer w0.2: v1(18.9,58.3) 18.9,57.7 20,56.6 U1.AB21@20,50.5
  Bottom Layer w0.2: v1(18.9,58.3) HDR1.11@18.9,60.5
BLUE0: HDR1.14 U1.L18 | length 59
  Top Layer w0.2: v1(22.5,40) U1.L18@23,39.5
  MidLayer2 w0.127: 20,40.5 22,40.5
  MidLayer2 w0.2: 20,40.5 15.8,44.7 12.1,44.7 11.6,44.2 10.5,44.2 9.4,45.3 9.4,57.7 13.5,61.8 13.5,66.4 11.1,68.8 11.1,71.2 12.1,72.2 18.9,72.2 v1(20.3,70.8) ; 22,40.5 v1(22.5,40)
  Bottom Layer w0.2: HDR1.14@19.7,67.3 19.7,70 19.7,70.2 v1(20.3,70.8)
BLUE1: HDR1.16 U1.M21 | length 53.1
  Top Layer w0.2: v1(16.7,39.9) 17.3,39.9 17.5,40.1 18.5,40.1 18.6,40 19.5,40 U1.M21@20,40.5
  MidLayer1 w0.2: v1(12.2,70.2) 12.2,61.4 8.4,57.6 8.4,42.5 10.8,40.1 15.6,40.1 15.8,39.9 v1(16.7,39.9)
  MidLayer2 w0.2: v1(12.2,70.2) 12.6,70.6 18.5,70.6 20.1,69 v1(20.5,69)
  Bottom Layer w0.2: HDR1.16@20.5,67.3 v1(20.5,69)
BOC_CTS: HDR1.13 U1.V20 | length 16.3
  Top Layer w0.2: v1(20.5,47) U1.V20@21,46.5
  MidLayer1 w0.2: v1(19.3,56.4) 19.3,54.7 19.9,54.1 19.9,51.4 19.637,51.137 19.637,51.102 18.9,50.366 18.9,47.5 19.4,47 v1(20.5,47)
  Bottom Layer w0.2: v1(19.3,56.4) 19.3,57.7 19.7,58.1 HDR1.13@19.7,60.5
BOC_RTS: HDR1.17 U1.M20 | length 40.6
  Top Layer w0.2: v1(20.5,41) U1.M20@21,40.5
  MidLayer1 w0.2: v1(11.3,56.5) 10,55.2 10,44.4 12.4,42 14.5,42 15,42.5 18.1,42.5 19.6,41 v1(20.5,41)
  MidLayer2 w0.2: v1(11.3,56.5) 14.9,56.5 16,55.4 20.2,55.4 v1(21.3,56.5)
  Bottom Layer w0.2: v1(21.3,56.5) HDR1.17@21.3,60.5
BOC_RX: HDR1.19 U1.L17 | length 22.3
  Top Layer w0.2: v1(23.5,40) U1.L17@24,39.5
  MidLayer1 w0.127: 23,45.5 23,48.5 ; 24,40.5 24,43.5
  MidLayer1 w0.2: v1(22.3,59) 22.3,56.4 23.1,55.6 23.1,48.6 23,48.5 ; 23,45.5 23.2,45.3 23.2,44.3 24,43.5 ; v1(23.5,40) 24,40.5
  Bottom Layer w0.2: HDR1.19@22.1,60.5 22.1,59.2 v1(22.3,59)
BOC_TX: HDR1.15 U1.Y21 | length 12.6
  Top Layer w0.2: U1.Y21@20,48.5 20.5,49 20.5,57 v1(20,57.5)
  Bottom Layer w0.2: v1(20,57.5) 20.5,58 HDR1.15@20.5,60.5
BUZZER: HDR2.24 U1.E17 | length 17.6
  Top Layer w0.2: v1(23.5,33) U1.E17@24,33.5
  MidLayer3 w0.127: 24,30.5 24,32.5
  MidLayer3 w0.2: v1(23.5,33) 24,32.5 ; v1(23.7,19.5) 24.1,19.9 24.1,24.5 24,24.6 24,30.5
  Bottom Layer w0.2: HDR2.24@23.7,16.5 v1(23.7,19.5)
CAN_RXD: HDR1.4 U1.W22 | length 26.7
  Top Layer w0.2: v1(16.4,57.7) 16.4,57.1 18.3,55.2 18.3,53.1 16.8,51.6 16.8,50.6 16.4,50.2 16.4,49.1 18,47.5 U1.W22@19,47.5
  MidLayer1 w0.2: v1(15.7,69) 15.7,67.2 15.9,67 15.9,58.2 v1(16.4,57.7)
  Bottom Layer w0.2: HDR1.4@15.7,67.3 v1(15.7,69)
CAN_TXD: HDR1.2 U1.V22 | length 30.2
  Top Layer w0.2: v1(13.9,57.5) 16.5,54.9 16.5,52.5 16,52 16,50.966 15.6,50.566 15.6,48.7 17.8,46.5 U1.V22@19,46.5
  MidLayer1 w0.2: v1(13.9,57.5) 13.9,68 14.9,69 v1(14.9,70)
  Bottom Layer w0.2: HDR1.2@14.9,67.3 v1(14.9,70)
DXN: C8.1 R18.2 U1.C5 U2.4 | length 72.4
  Top Layer w0.2: v1(35.5,31) U1.C5@36,31.5
  Top Layer w0.3: R18.2@2.5,3.95 C8.1@2.5,5.65 ; 2.5,4.8 v1(4.7,4.8) 5.218,5.318 U2.4@6.4,5.318
  MidLayer1 w0.2: v1(4.7,4.8) 4.7,4.566 7.666,1.6 37.7,1.6 37.9,1.8 37.9,6.2 37.5,6.6 37.5,7.3 37.9,7.7 37.9,13.7 34.9,16.7 34.9,23.2 35.6,23.9 35.6,24.6 35.5,24.7 v1(35.5,31)
DXP: C8.2 U1.C4 U2.3 | length 75.2
  Top Layer w0.2: v1(36.5,31) U1.C4@37,31.5
  Top Layer w0.3: C8.2@2.5,7.35 3.35,7.35 4.747,5.953 U2.3@6.4,5.953
  MidLayer1 w0.2: v1(3.9,6.8) 3.9,4.8 7.5,1.2 38,1.2 38.3,1.5 38.3,6.2 38.7,6.6 38.7,7.3 38.3,7.7 38.3,13.866 36.893,15.293 ; 36,16.166 35.3,16.866 35.3,20.7 36.4,21.8 36.4,24.8 35.9,25.3 35.9,30.3 36.5,30.9 v1(36.5,31) ; 36.017,16.183 36.9,15.3
FPGA_AUX0: R6.1 U1.A2 | length 61.4
  Top Layer w0.2: U1.A2@39,29.5 40.6,27.9 v1(41.2,27.9)
  MidLayer3 w0.2: v1(47,25.6) 47,31.7 46.1,32.6 46.1,39.8 47.8,41.5 47.8,50.5 50.1,52.8 50.1,56.5 51.2,57.6 51.2,61.8 51.5,62.1 51.5,69.6 v1(50.1,71)
  Bottom Layer w0.2: v1(41.2,27.9) 42.266,27.9 44.566,25.6 v1(47,25.6) ; R6.1@48.5,72.95 49.45,72.95 50.1,72.3 v1(50.1,71)
FPGA_AUX1: HDR1.88 U1.Y1 | length 26.6
  Top Layer w0.2: U1.Y1@40,48.5 40.5,48.5 46.9,54.9 v1(46.9,56.7)
  MidLayer1 w0.2: v1(46.9,56.7) 47.5,57.3 47.5,58 46.9,58.6 46.9,62.5 49.3,64.9 v1(49.3,68.9)
  Bottom Layer w0.2: HDR1.88@49.3,67.3 v1(49.3,68.9)
FPGA_AUX2: HDR1.90 U1.N2 | length 40.1
  Top Layer w0.2: U1.N2@39,41.5 39.5,41 40.368,41 40.468,41.1 42.2,41.1 42.5,40.8 v1(43.7,40.8)
  MidLayer3 w0.2: v1(43.7,40.8) 47,44.1 47,54 47.5,54.5 47.5,58.2 47.1,58.6 47.1,60.3 50.1,63.3 v1(50.1,70)
  Bottom Layer w0.2: HDR1.90@50.1,67.2 HDR1.90@50.1,67.3 v1(50.1,70)
FPGA_AUX3: HDR1.92 U1.M2 | length 38.7
  Top Layer w0.2: U1.M2@39,40.5 39.5,40 40.368,40 40.468,39.9 v1(44,39.9)
  MidLayer3 w0.2: v1(44,39.9) 47.4,43.3 47.4,53.7 47.9,54.2 47.9,58.2 48.3,58.6 48.3,60 50.9,62.6 v1(50.9,68.9)
  Bottom Layer w0.2: HDR1.92@50.9,67.3 v1(50.9,68.9)
FPGA_CCLK: R7.2 U1.W20 | length 45.6
  Top Layer w0.2: U1.W20@21,47.5 v1(21.5,48)
  MidLayer2 w0.2: v1(23.4,73) 23.8,73 24,73.2 25.1,73.2 25.3,73 39.3,73 v1(40.5,74.2)
  MidLayer3 w0.2: v1(21.5,48) 21.5,54.4 22.9,55.8 22.9,69 23.4,69.5 23.4,69.833 23.5,69.933 23.5,70.8 23.4,70.9 v1(23.4,73)
  Bottom Layer w0.2: R7.2@40.5,72.95 v1(40.5,74.2)
FPGA_CCLK_R: HDR1.66 R7.1 TP1.1 | length 3.8
  Bottom Layer w0.2: HDR1.66@40.5,67.3 TP1.1@40.5,69.5 R7.1@40.5,71.05
FPGA_CLK: HDR2.2 TP9.1 U1.D11 | length 30.1
  Top Layer w0.2: v1(29.5,32) U1.D11@30,32.5
  MidLayer2 w0.127: 29,30.5 29,31.5
  MidLayer2 w0.2: v1(28.7,24.5) 28.7,26.5 28.4,26.8 28.4,28.6 29,29.2 29,30.5 ; 29,31.5 v1(29.5,32)
  Bottom Layer w0.2: HDR2.2@14.9,16.5 14.9,18.9 TP9.1@15,19 14.2,19.8 14.2,21.9 14.8,22.5 19.6,22.5 19.8,22.7 24.3,22.7 25.1,23.5 26.8,23.5 27.8,24.5 v1(28.7,24.5)
FPGA_CLK_1: HDR1.30 U1.Y12 | length 26.1
  Top Layer w0.2: v1(28.5,49) U1.Y12@29,48.5
  MidLayer1 w0.2: v1(25.4,70) 27.1,68.3 27.1,58.034 27.8,57.334 27.8,52 28.5,51.3 v1(28.5,49)
  Bottom Layer w0.2: v1(25.4,70) 26.1,69.3 HDR1.30@26.1,67.3 HDR1.30@26.1,67.2
FPGA_CLK_2: HDR1.32 U1.U11 | length 34.2
  Top Layer w0.2: v1(29.5,46) U1.U11@30,45.5
  MidLayer1 w0.127: 30,46.5 30,48.5
  MidLayer1 w0.2: v1(25.3,71.6) 26.6,71.6 27.9,70.3 27.9,58.4 28.6,57.7 28.6,55.4 29.6,54.4 29.6,50.1 29.9,49.8 29.9,48.6 30,48.5 ; v1(29.5,46) 30,46.5
  Bottom Layer w0.2: v1(25.3,71.6) 26.9,70 HDR1.32@26.9,67.3
FPGA_DIN: HDR1.64 U1.V17 | length 46
  Top Layer w0.2: v1(23.5,46) U1.V17@24,46.5
  MidLayer2 w0.2: v1(24.1,70.8) 24.5,70.8 24.7,70.6 29.5,70.6 29.8,70.3 32.1,70.3 32.5,70.7 36.2,70.7 36.8,70.1 v1(39.3,70.1)
  MidLayer3 w0.127: 23,46.5 23,48.5
  MidLayer3 w0.2: 23,46.5 v1(23.5,46) ; 23,48.5 24,49.5 24,51.3 24.9,52.2 24.9,57.8 24.3,58.4 24.3,68.2 24.4,68.3 24.4,69.3 23.9,69.8 23.9,70.2 24.1,70.4 v1(24.1,70.8) ; v1@23.9,70.8 v1@24,70.9
  Bottom Layer w0.2: v1(39.3,70.1) 39.3,68.8 39.7,68.4 HDR1.64@39.7,67.3
FPGA_DONE: R4.1 R14.1 U1.Y18 U5.2 | length 161.1
  Top Layer w0.2: v1(21,7) 21.4,7.4 24.1,7.4 24.5,7 24.5,5.6 24.609,5.491 U5.2@25.57,5.491 ; U1.Y18@23,48.5 v1(23.5,48) ; 26.9,2.8 26.9,2.4 27.2,2.1 R14.1@28.05,2.1
  Top Layer w0.3: U5.2@25.57,5.491 26.609,5.491 26.9,5.2 26.9,2.8
  MidLayer1 w0.2: v1(22,73.4) 22,70 22.424,69.576 23.1,68.9 23.1,56.3 23.5,55.9 v1(23.5,48)
  MidLayer2 w0.2: v1(21,7) 20.5,7.5 20.5,18.3 19.6,19.2 19.6,24.7 17.5,26.8 7.922,36.378 7.3,37 7.3,58.066 11.8,62.566 11.8,65.6 9.5,67.9 9.5,72.1 11.2,73.8 20.5,73.8 20.9,73.4 v1(22,73.4) 24.648,76.048 24.648,78.048 26.8,80.2 30.1,80.2 30.5,80.6 38,80.6 38.9,81.5 42.3,81.5 43.4,80.4 43.4,78.5 42,77.1 42,76 v1(43.5,74.5)
  Bottom Layer w0.2: R4.1@43,72.95 R4.1@43.5,72.95 v1(43.5,74.5)
FPGA_INIT: HDR1.68 R13.2 U1.W17 | length 55.5
  Top Layer w0.2: U1.W17@24,47.5 v1(24.5,47)
  MidLayer2 w0.2: v1(26.1,76.7) v1(39.4,76.7)
  MidLayer3 w0.127: 25,47.5 25,50.5
  MidLayer3 w0.2: v1(24.5,47) 25,47.5 ; 25,50.5 25.356,50.856 25.356,57.344 25.356,58.044 24.7,58.7 24.7,60.6 26.1,62 26.1,70.5 25.9,70.7 25.9,75.657 26.1,75.857 v1(26.1,76.7)
  Bottom Layer w0.2: R13.2@40.5,75.05 41.6,73.95 41.6,68.9 41.3,68.6 HDR1.68@41.3,67.3
  Bottom Layer w0.3: v1(39.4,76.7) 39.4,76.2 40.05,75.55 R13.2@40.7,75.55
FPGA_M0: R3.1 U1.Y4 | length 37.8
  Top Layer w0.2: v1(36.5,49) U1.Y4@37,48.5
  MidLayer3 w0.2: v1(34.1,79.5) 33.4,78.8 33.4,75.3 36.7,72 36.7,60.8 33.8,57.9 33.8,56.5 35.158,55.142 35.158,51.842 36.5,50.5 v1(36.5,49)
  Bottom Layer w0.2: v1(34.1,79.5) 34.9,79.5 35.5,78.9 R3.1@35.5,77.95
FPGA_M1: R2.1 U1.W3 | length 33.3
  Top Layer w0.2: U1.W3@38,47.5 v1(38.5,48)
  MidLayer3 w0.2: v1(34,75.8) 37.1,72.7 37.1,58.334 36.7,57.934 36.7,57.366 37.266,56.8 37.3,56.8 38.3,55.8 38.3,50.5 38.8,50 38.8,48.3 v1(38.5,48) v1@38.5,47.9
  Bottom Layer w0.2: v1(34,75.8) 34,74.95 R2.1@35,73.95
FPGA_M2: R1.1 U1.Y5 | length 34.8
  Top Layer w0.2: v1(35.5,49) U1.Y5@36,48.5
  MidLayer3 w0.2: v1(32.5,78.2) 32.5,75.634 36.3,71.834 36.3,61.1 33.4,58.2 33.4,56.334 33.9,55.834 33.9,51.7 35.5,50.1 v1(35.5,49)
  Bottom Layer w0.2: R1.1@32.5,76.95 v1(32.5,78.2)
FPGA_PROGRAM: R8.2 TP2.1 U1.B1 | length 71.7
  Top Layer w0.2: v1(39.5,30) U1.B1@40,30.5
  MidLayer3 w0.2: TP2.1@40,80 40,79.4 41.7,77.7 41.7,59.433 42.4,58.733 42.4,58.3 42.7,58 42.7,47.7 42.1,47.1 42.1,40.2 44,38.3 44,28.3 v1(44.8,27.5)
  Bottom Layer w0.2: R8.2@38,73.95 36.6,75.35 36.6,78.7 37.9,80 TP2.1@40,80 ; v1(39.5,30) 40,30.5 41,30.5 44,27.5 v1(44.8,27.5)
FPGA_PROGRAM_R: HDR1.62 R8.1 R11.1 | length 10.7
  Bottom Layer w0.2: R8.1@38,72.05 39.1,72.05 ; R11.1@38,76.05 38.15,76.05 39.1,75.1 39.1,71 38.6,70.5 38.6,69.5 38.9,69.2 HDR1.62@38.9,67.3
FPGA_TCK: HDR1.72 TP5.1 U1.B22 | length 100.3
  Top Layer w0.2: v1(18.5,30) U1.B22@19,30.5
  MidLayer2 w0.2: v1(18.5,30) 15.5,30 9.5,36 9.5,40.234 8.2,41.534 8.2,57.8 8.925,58.525 12.7,62.3 12.7,65.934 10.3,68.334 10.3,71.7 11.6,73 19.5,73 20.6,71.9 24.6,71.9 25.2,72.5 42.7,72.5 44.3,74.1 44.3,75.7 TP5.1@43.5,76.5
  Bottom Layer w0.2: HDR1.72@42.9,67.3 42.9,68.7 42.4,69.2 42.4,74.4 43.5,75.5 TP5.1@43.5,76.5 TP5.1@43,76.5
FPGA_TDI: HDR1.78 TP3.1 U1.D3 | length 74
  Top Layer w0.2: U1.D3@38,32.5 v1(38.5,32)
  MidLayer1 w0.2: v1(38.5,32) 40,32 43.1,28.9 v1(44.7,28.9)
  MidLayer3 w0.2: v1(44.7,28.9) 44.7,30.5 44.4,30.8 44.4,38.5 42.5,40.4 42.5,45.4 43.7,46.6 44.8,47.7 44.8,50.5 45.9,51.6 45.9,58.1 45.3,58.7 45.3,77.3 TP3.1@47,79
  Bottom Layer w0.2: HDR1.78@45.3,67.3 45.3,72.4 45.8,72.9 46.2,73.3 46.7,73.8 46.7,77.8 47,78.1 TP3.1@47,79
FPGA_TDO: R9.2 R12.2 U1.D20 | length 85.5
  Top Layer w0.2: v1(20.5,32) U1.D20@21,32.5
  MidLayer2 w0.2: v1(20.5,32) 19.6,32.9 15.8,32.9 15.5,33.2 12.9,33.2 9.9,36.2 9.9,40.4 8.6,41.7 8.6,57.6 13.1,62.1 13.1,66.1 10.7,68.5 10.7,71.5 11.8,72.6 19.2,72.6 20.4,71.4 24.466,71.4 24.866,71 27.8,71 28.6,71.8 v1(30.7,71.8)
  Bottom Layer w0.2: R12.2@30.4,82 30.4,80.4 29.977,79.977 29.977,77.423 30.8,76.6 30.8,73 30.7,72.9 v1(30.7,71.8) 31.5,71.5 R9.2@32,71.05
FPGA_TDO_R: HDR1.54 R9.1 TP4.1 | length 16.4
  Bottom Layer w0.2: TP4.1@30.8,78.9 TP4.1@30.9,78.9 ; TP4.1@31.5,79 31.3,78.8 31.3,74.1 31.4,74 32,74 ; R9.1@32,72.95 32,74 ; HDR1.54@35.7,67.3 35.7,69.834 35.134,70.4 33.7,70.4 33.3,70.8 33.3,73.5 32.8,74 32,74
FPGA_TMS: HDR1.70 TP6.1 U1.A21 | length 103.3
  Top Layer w0.2: v1(19.4,28.8) 19.4,28.9 U1.A21@20,29.5
  MidLayer2 w0.2: v1(19.4,28.8) 18.7,28.1 16.8,28.1 9.1,35.8 9.1,40.069 7.8,41.369 7.8,58 8.4,58.6 12.3,62.5 12.3,65.769 9.9,68.169 9.9,71.9 11.4,73.4 19.8,73.4 20.7,72.5 21.9,72.5 25.2,75.8 25.2,76.9 25.8,77.5 27.7,77.5 27.9,77.3 38.7,77.3 38.9,77.5 40,77.5 TP6.1@42,79.5
  Bottom Layer w0.2: TP6.1@42,79.5 42,68.7 42.1,68.6 HDR1.70@42.1,67.3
